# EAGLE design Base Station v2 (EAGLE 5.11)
OC_FARNELL: 1741293

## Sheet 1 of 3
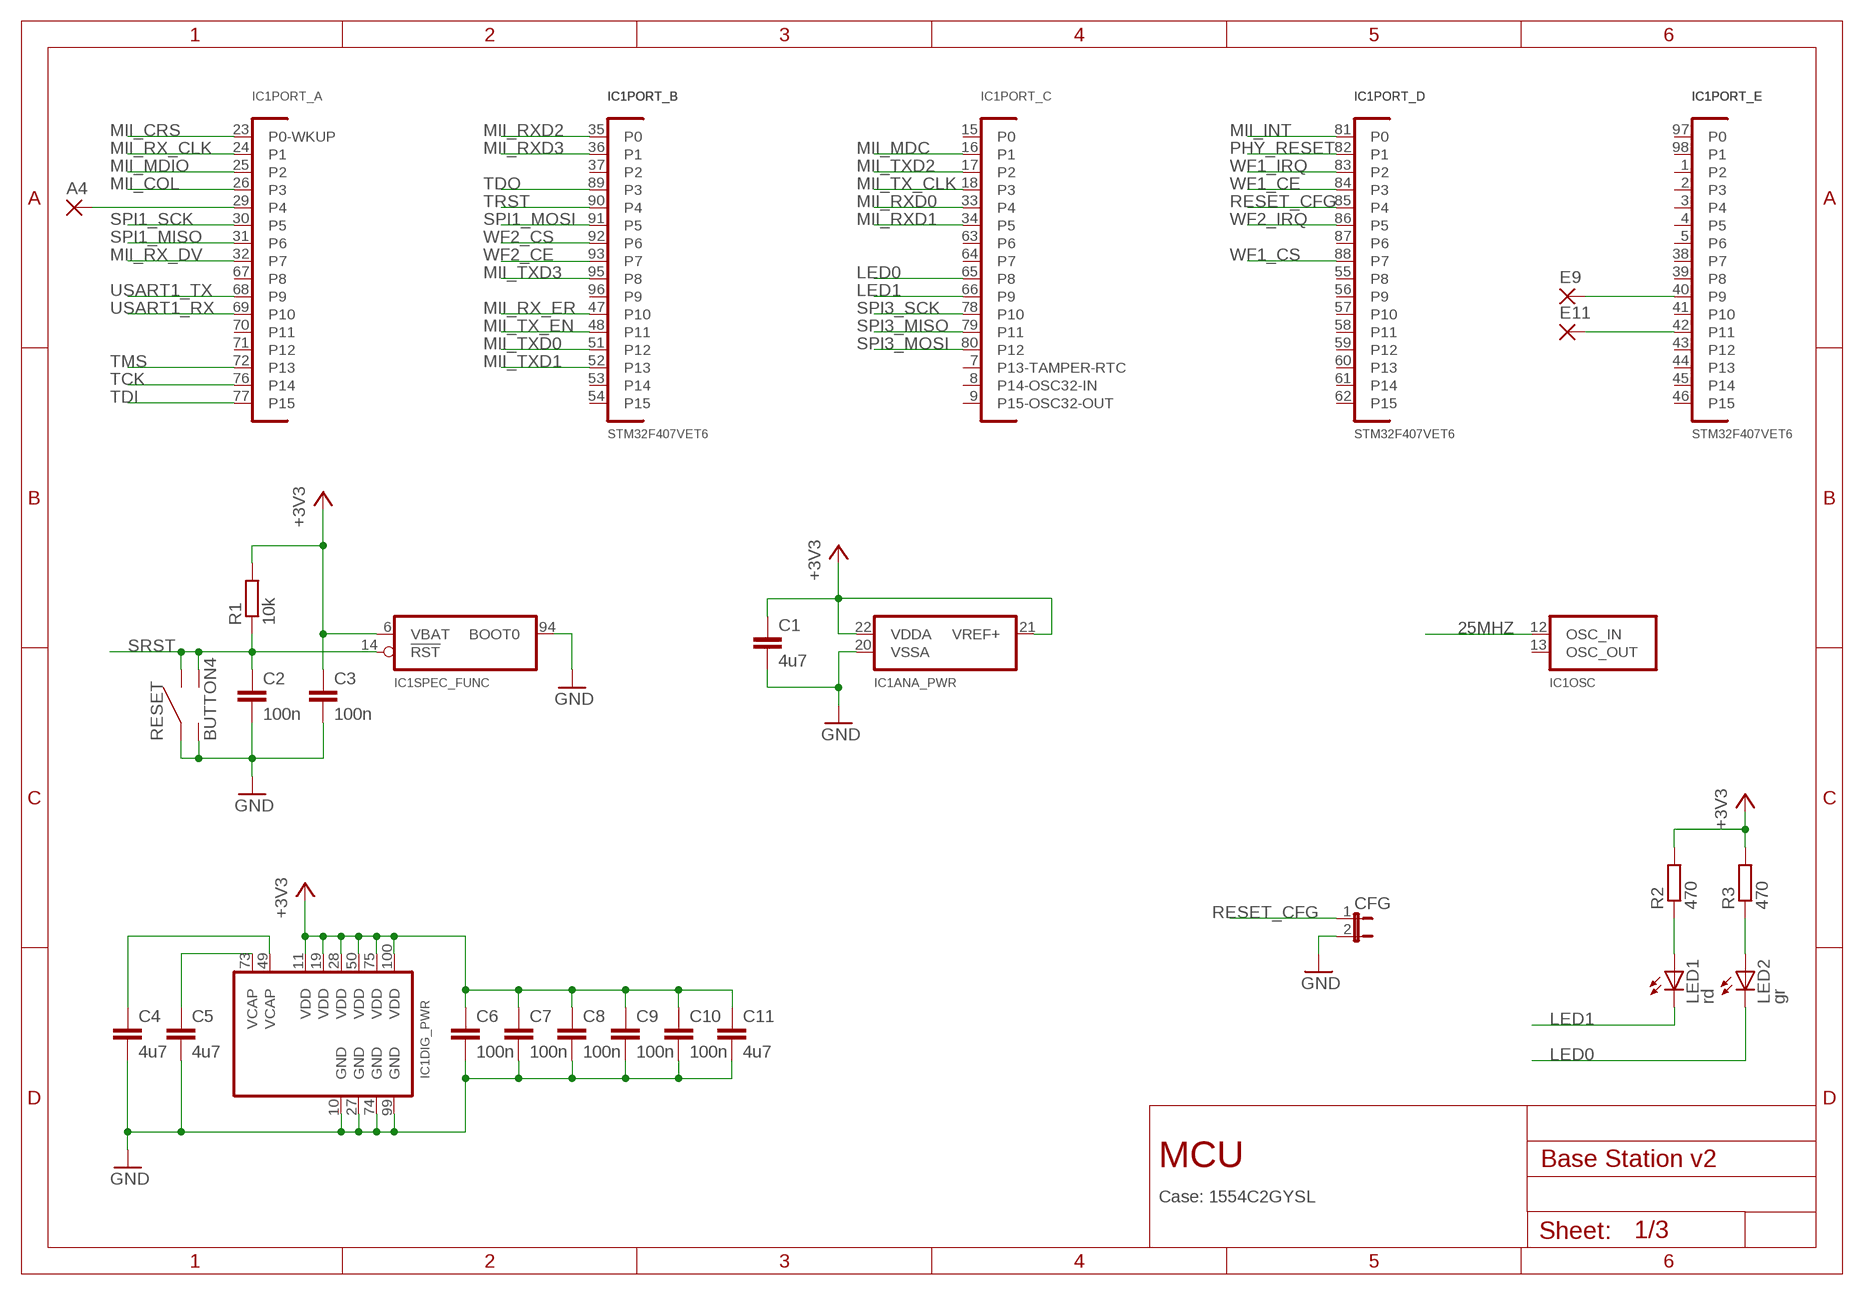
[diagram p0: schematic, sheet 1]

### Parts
A4  1,6/0,9  [1,6/0,9]
C1  4u7  C-EUC0603  [C0603]
C2  100n  C-EUC0603  [C0603]
C3  100n  C-EUC0603  [C0603]
C4  4u7  C-EUC0603  [C0603]
C5  4u7  C-EUC0603  [C0603]
C6  100n  C-EUC0603  [C0603]
C7  100n  C-EUC0603  [C0603]
C8  100n  C-EUC0603  [C0603]
C9  100n  C-EUC0603  [C0603]
C10  100n  C-EUC0603  [C0603]
C11  4u7  C-EUC0603  [C0603]
CFG  JP1E  [JP1]
E9  1,6/0,9  [1,6/0,9]
E11  1,6/0,9  [1,6/0,9]
IC1  STM32F407VET6  STM32F40_VST  [LQFP100-ST]
LED1  rd  LEDCHIP-LED0603  [CHIP-LED0603]
LED2  gr  LEDCHIP-LED0603  [CHIP-LED0603]
R1  10k  R-EU_R0603  [R0603]
R2  470  R-EU_R0603  [R0603]
R3  470  R-EU_R0603  [R0603]
RESET  BUTTON4  [BUTTON4]

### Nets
25MHZ: IC1.12(OSC:OSC_IN) ; also sheet 3
+3V3: C1.1 C3.1 C6.1 C7.1 C8.1 C9.1 C10.1 C11.1 IC1.6(SPEC_FUNC:VBAT) IC1.11(DIG_PWR:VDD) IC1.19(DIG_PWR:VDD) IC1.21(ANA_PWR:VREF+) IC1.22(ANA_PWR:VDDA) IC1.28(DIG_PWR:VDD) IC1.50(DIG_PWR:VDD) IC1.75(DIG_PWR:VDD) IC1.100(DIG_PWR:VDD) R1.2 R2.2 R3.2 ; also sheet 2,3
DAC1: A4.1(P) IC1.29(PORT_A:P4)
GND: C1.2 C2.2 C3.2 C4.2 C5.2 C6.2 C7.2 C8.2 C9.2 C10.2 C11.2 CFG.2 IC1.10(DIG_PWR:GND) IC1.20(ANA_PWR:VSSA) IC1.27(DIG_PWR:GND) IC1.74(DIG_PWR:GND) IC1.94(SPEC_FUNC:BOOT0) IC1.99(DIG_PWR:GND) RESET.1 RESET.2 ; also sheet 2,3
LED0: IC1.65(PORT_C:P8) LED2.C
LED1: IC1.66(PORT_C:P9) LED1.C
MII_COL: IC1.26(PORT_A:P3) ; also sheet 3
MII_CRS: IC1.23(PORT_A:P0-WKUP) ; also sheet 3
MII_INT: IC1.81(PORT_D:P0) ; also sheet 3
MII_MDC: IC1.16(PORT_C:P1) ; also sheet 3
MII_MDIO: IC1.25(PORT_A:P2) ; also sheet 3
MII_RX_CLK: IC1.24(PORT_A:P1) ; also sheet 3
MII_RX_DV: IC1.32(PORT_A:P7) ; also sheet 3
MII_RX_ER: IC1.47(PORT_B:P10) ; also sheet 3
MII_RXD0: IC1.33(PORT_C:P4) ; also sheet 3
MII_RXD1: IC1.34(PORT_C:P5) ; also sheet 3
MII_RXD2: IC1.35(PORT_B:P0) ; also sheet 3
MII_RXD3: IC1.36(PORT_B:P1) ; also sheet 3
MII_TX_CLK: IC1.18(PORT_C:P3) ; also sheet 3
MII_TX_EN: IC1.48(PORT_B:P11) ; also sheet 3
MII_TXD0: IC1.51(PORT_B:P12) ; also sheet 3
MII_TXD1: IC1.52(PORT_B:P13) ; also sheet 3
MII_TXD2: IC1.17(PORT_C:P2) ; also sheet 3
MII_TXD3: IC1.95(PORT_B:P8) ; also sheet 3
N$31: E9.1(P) IC1.40(PORT_E:P9)
N$32: E11.1(P) IC1.42(PORT_E:P11)
N$62: C5.1 IC1.73(DIG_PWR:VCAP)
N$63: C4.1 IC1.49(DIG_PWR:VCAP)
N$67: LED2.A R3.1
N$68: LED1.A R2.1
PHY_RESET: IC1.82(PORT_D:P1) ; also sheet 3
RESET_CFG: CFG.1 IC1.85(PORT_D:P4)
SPI1_MISO: IC1.31(PORT_A:P6) ; also sheet 2
SPI1_MOSI: IC1.91(PORT_B:P5) ; also sheet 2
SPI1_SCK: IC1.30(PORT_A:P5) ; also sheet 2
SPI3_MISO: IC1.79(PORT_C:P11) ; also sheet 2
SPI3_MOSI: IC1.80(PORT_C:P12) ; also sheet 2
SPI3_SCK: IC1.78(PORT_C:P10) ; also sheet 2
SRST: C2.1 IC1.14(SPEC_FUNC:!RST) R1.1 RESET.3 RESET.4 ; also sheet 2
TCK: IC1.76(PORT_A:P14) ; also sheet 2
TDI: IC1.77(PORT_A:P15) ; also sheet 2
TDO: IC1.89(PORT_B:P3) ; also sheet 2
TMS: IC1.72(PORT_A:P13) ; also sheet 2
TRST: IC1.90(PORT_B:P4) ; also sheet 2
USART1_RX: IC1.69(PORT_A:P10) ; also sheet 2
USART1_TX: IC1.68(PORT_A:P9) ; also sheet 2
WF1_CE: IC1.84(PORT_D:P3) ; also sheet 2
WF1_CS: IC1.88(PORT_D:P7) ; also sheet 2
WF1_IRQ: IC1.83(PORT_D:P2) ; also sheet 2
WF2_CE: IC1.93(PORT_B:P7) ; also sheet 2
WF2_CS: IC1.92(PORT_B:P6) ; also sheet 2
WF2_IRQ: IC1.86(PORT_D:P5) ; also sheet 2
Unconnected: IC1.1(PORT_E:P2) IC1.2(PORT_E:P3) IC1.3(PORT_E:P4) IC1.4(PORT_E:P5) IC1.5(PORT_E:P6) IC1.7(PORT_C:P13-TAMPER-RTC) IC1.8(PORT_C:P14-OSC32-IN) IC1.9(PORT_C:P15-OSC32-OUT) IC1.13(OSC:OSC_OUT) IC1.15(PORT_C:P0) IC1.37(PORT_B:P2) IC1.38(PORT_E:P7) IC1.39(PORT_E:P8) IC1.41(PORT_E:P10) IC1.43(PORT_E:P12) IC1.44(PORT_E:P13) IC1.45(PORT_E:P14) IC1.46(PORT_E:P15) IC1.53(PORT_B:P14) IC1.54(PORT_B:P15) IC1.55(PORT_D:P8) IC1.56(PORT_D:P9) IC1.57(PORT_D:P10) IC1.58(PORT_D:P11) IC1.59(PORT_D:P12) IC1.60(PORT_D:P13) IC1.61(PORT_D:P14) IC1.62(PORT_D:P15) IC1.63(PORT_C:P6) IC1.64(PORT_C:P7) IC1.67(PORT_A:P8) IC1.70(PORT_A:P11) IC1.71(PORT_A:P12) IC1.87(PORT_D:P6) IC1.96(PORT_B:P9) IC1.97(PORT_E:P0) IC1.98(PORT_E:P1)

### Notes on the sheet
- MCU
- Case: 1554C2GYSL

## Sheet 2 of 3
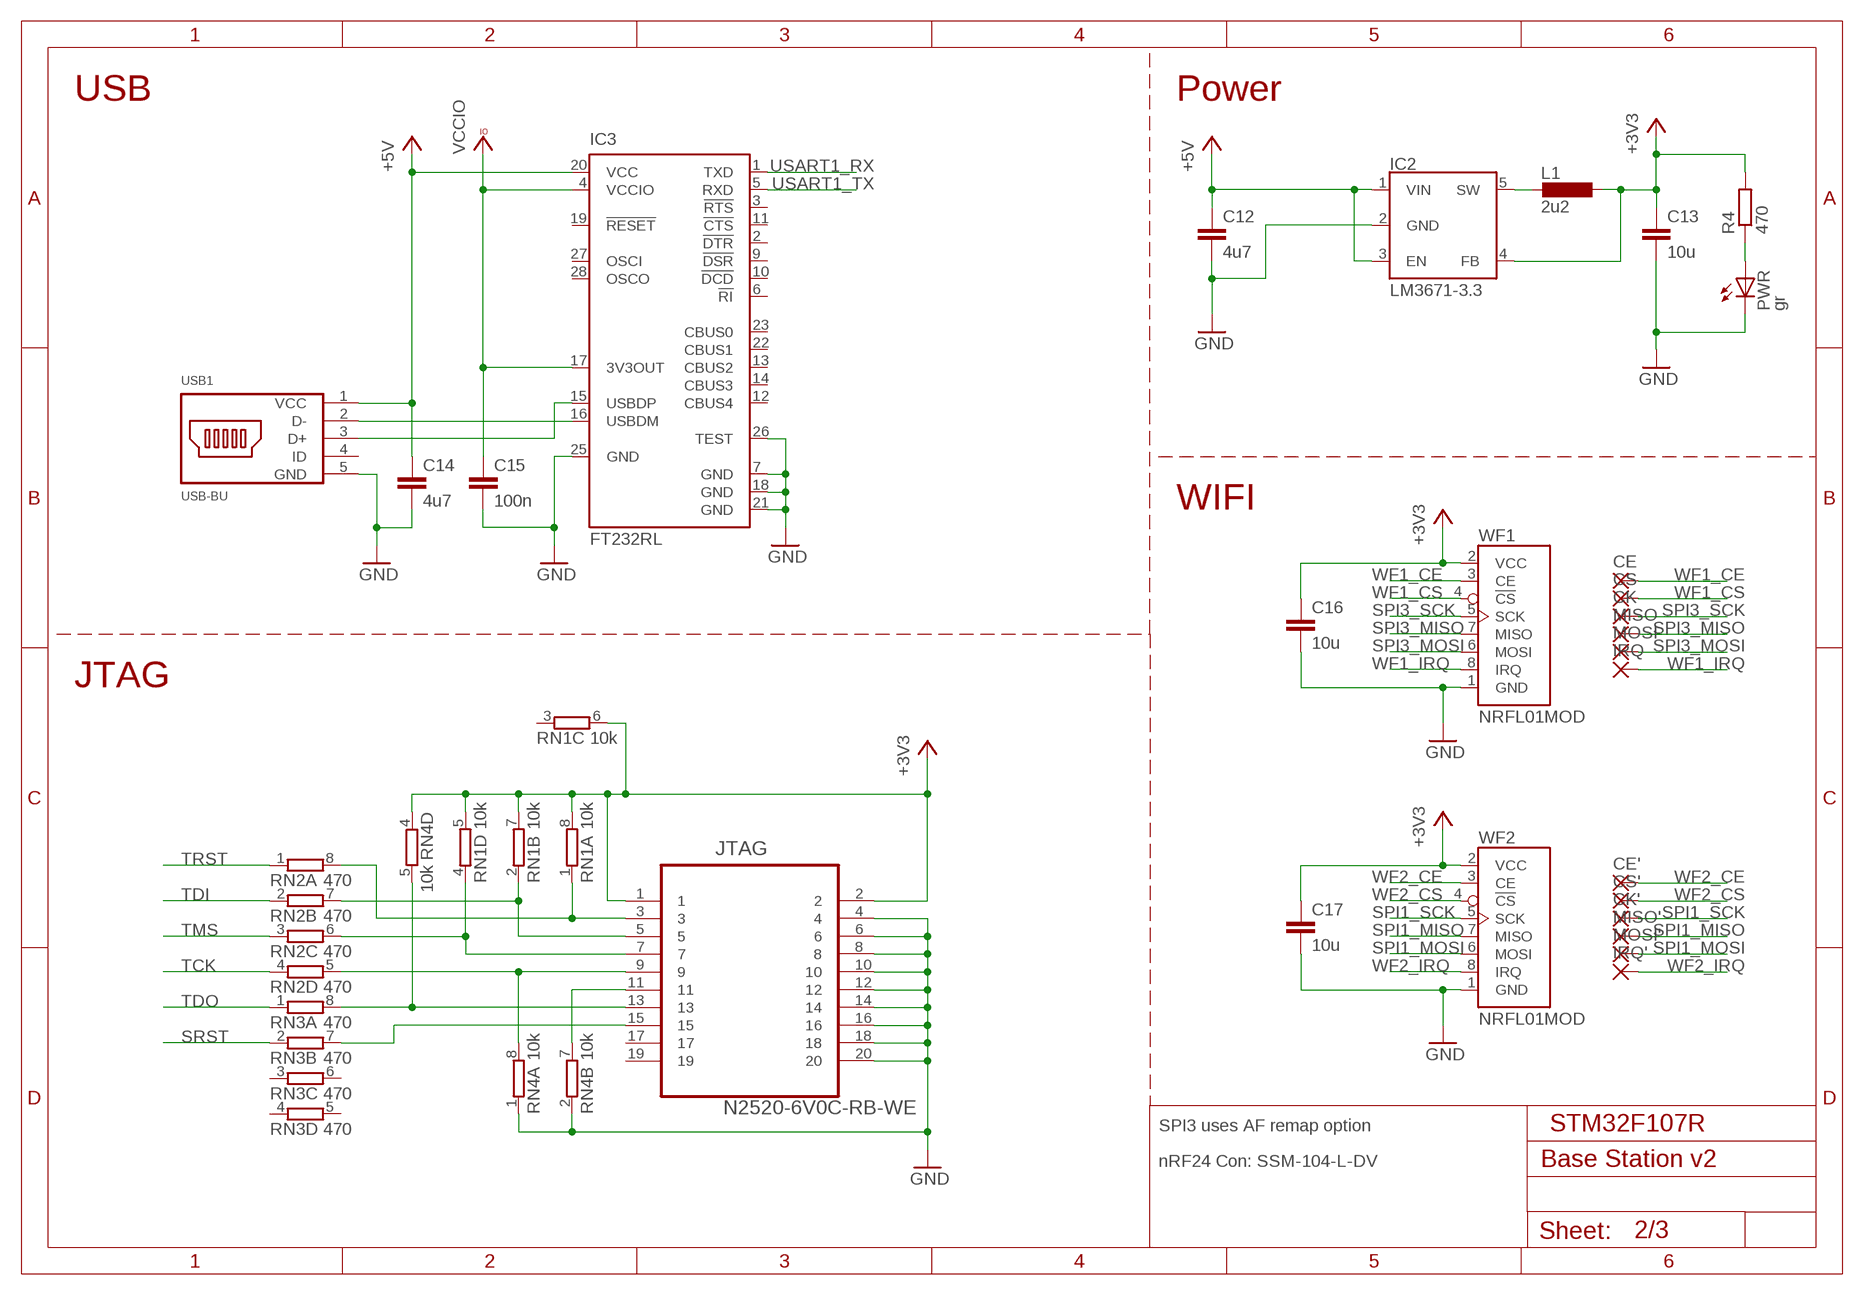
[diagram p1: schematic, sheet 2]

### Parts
C12  4u7  C-EUC0603  [C0603]
C13  10u  C-EUC0805  [C0805]
C14  4u7  C-EUC0603  [C0603]
C15  100n  C-EUC0603  [C0603]
C16  10u  C-EUC0805  [C0805]
C17  10u  C-EUC0805  [C0805]
CE  1,6/0,9  [1,6/0,9]
CE'  1,6/0,9  [1,6/0,9]
CK  1,6/0,9  [1,6/0,9]
CK'  1,6/0,9  [1,6/0,9]
CS  1,6/0,9  [1,6/0,9]
CS'  1,6/0,9  [1,6/0,9]
IC2  LM3671-3.3  LM3671  [SOT23-5]
IC3  FT232RL  [SSOP28]
IRQ  1,6/0,9  [1,6/0,9]
IRQ'  1,6/0,9  [1,6/0,9]
JTAG  N2520-6V0C-RB-WE  [3M_N2520-6V0C-RB-WE]
L1  2u2  LIHLP  [IHLP1616]
MISO  1,6/0,9  [1,6/0,9]
MISO'  1,6/0,9  [1,6/0,9]
MOSI  1,6/0,9  [1,6/0,9]
MOSI'  1,6/0,9  [1,6/0,9]
PWR  gr  LEDCHIP-LED0603  [CHIP-LED0603]
R4  470  R-EU_R0603  [R0603]
RN1  10k  4R-NEXB28V  [EXB28V]
RN2  470  4R-NEXB28V  [EXB28V]
RN3  470  4R-NEXB28V  [EXB28V]
RN4  10k  4R-NEXB28V  [EXB28V]
USB1  USB-BU  [USB-BMICRO]
WF1  NRFL01MOD  NRFL01MODN  [NRF24L01SMD]
WF2  NRFL01MOD  NRFL01MODN  [NRF24L01SMD]

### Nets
+3V3: C13.1 C16.1 C17.1 IC2.4(FB) JTAG.1 JTAG.2 L1.P$1 R4.2 RN1.5 RN1.6 RN1.7 RN1.8 RN4.4 WF1.2(VCC) WF2.2(VCC) ; also sheet 1,3
+5V: C12.1 C14.1 IC2.1(VIN) IC2.3(EN) IC3.20(VCC) USB1.1(VCC)
GND: C12.2 C13.2 C14.2 C15.2 C16.2 C17.2 IC2.2(GND) IC3.7(GND) IC3.18(GND) IC3.21(GND) IC3.25(GND) IC3.26(TEST) JTAG.4 JTAG.6 JTAG.8 JTAG.10 JTAG.12 JTAG.14 JTAG.16 JTAG.18 JTAG.20 PWR.C RN4.1 RN4.2 USB1.5(GND) WF1.1(GND) WF2.1(GND) ; also sheet 1,3
JTAG-SRST1: JTAG.15 RN3.7
JTAG-TCK1: JTAG.9 RN2.5 RN4.8
JTAG-TDI1: JTAG.5 RN1.2 RN2.7
JTAG-TDO1: JTAG.13 RN3.8 RN4.5
JTAG-TMS1: JTAG.7 RN1.4 RN2.6
JTAG-TRST1: JTAG.3 RN1.1 RN2.8
N$30: JTAG.11 RN4.7
N$41: IC3.16(USBDM) USB1.2(D-)
N$42: IC3.15(USBDP) USB1.3(D+)
N$45: IC2.5(SW) L1.P$2
N$48: PWR.A R4.1
SPI1_MISO: MISO'.1(P) WF2.7(MISO) ; also sheet 1
SPI1_MOSI: MOSI'.1(P) WF2.6(MOSI) ; also sheet 1
SPI1_SCK: CK'.1(P) WF2.5(SCK) ; also sheet 1
SPI3_MISO: MISO.1(P) WF1.7(MISO) ; also sheet 1
SPI3_MOSI: MOSI.1(P) WF1.6(MOSI) ; also sheet 1
SPI3_SCK: CK.1(P) WF1.5(SCK) ; also sheet 1
SRST: RN3.2 ; also sheet 1
TCK: RN2.4 ; also sheet 1
TDI: RN2.2 ; also sheet 1
TDO: RN3.1 ; also sheet 1
TMS: RN2.3 ; also sheet 1
TRST: RN2.1 ; also sheet 1
USART1_RX: IC3.1(TXD) ; also sheet 1
USART1_TX: IC3.5(RXD) ; also sheet 1
VCCIO: C15.1 IC3.4(VCCIO) IC3.17(3V3OUT)
WF1_CE: CE.1(P) WF1.3(CE) ; also sheet 1
WF1_CS: CS.1(P) WF1.4(!CS) ; also sheet 1
WF1_IRQ: IRQ.1(P) WF1.8(IRQ) ; also sheet 1
WF2_CE: CE'.1(P) WF2.3(CE) ; also sheet 1
WF2_CS: CS'.1(P) WF2.4(!CS) ; also sheet 1
WF2_IRQ: IRQ'.1(P) WF2.8(IRQ) ; also sheet 1
Unconnected: IC3.2(!DTR) IC3.3(!RTS) IC3.6(!RI) IC3.9(!DSR) IC3.10(!DCD) IC3.11(!CTS) IC3.12(CBUS4) IC3.13(CBUS2) IC3.14(CBUS3) IC3.19(!RESET) IC3.22(CBUS1) IC3.23(CBUS0) IC3.27(OSCI) IC3.28(OSCO) JTAG.17 JTAG.19 RN1.3 RN3.3 RN3.4 RN3.5 RN3.6 RN4.3 RN4.6 USB1.4(ID)

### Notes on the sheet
- USB | Power
- WIFI
- JTAG
- SPI3 uses AF remap option | STM32F107R
- nRF24 Con: SSM-104-L-DV

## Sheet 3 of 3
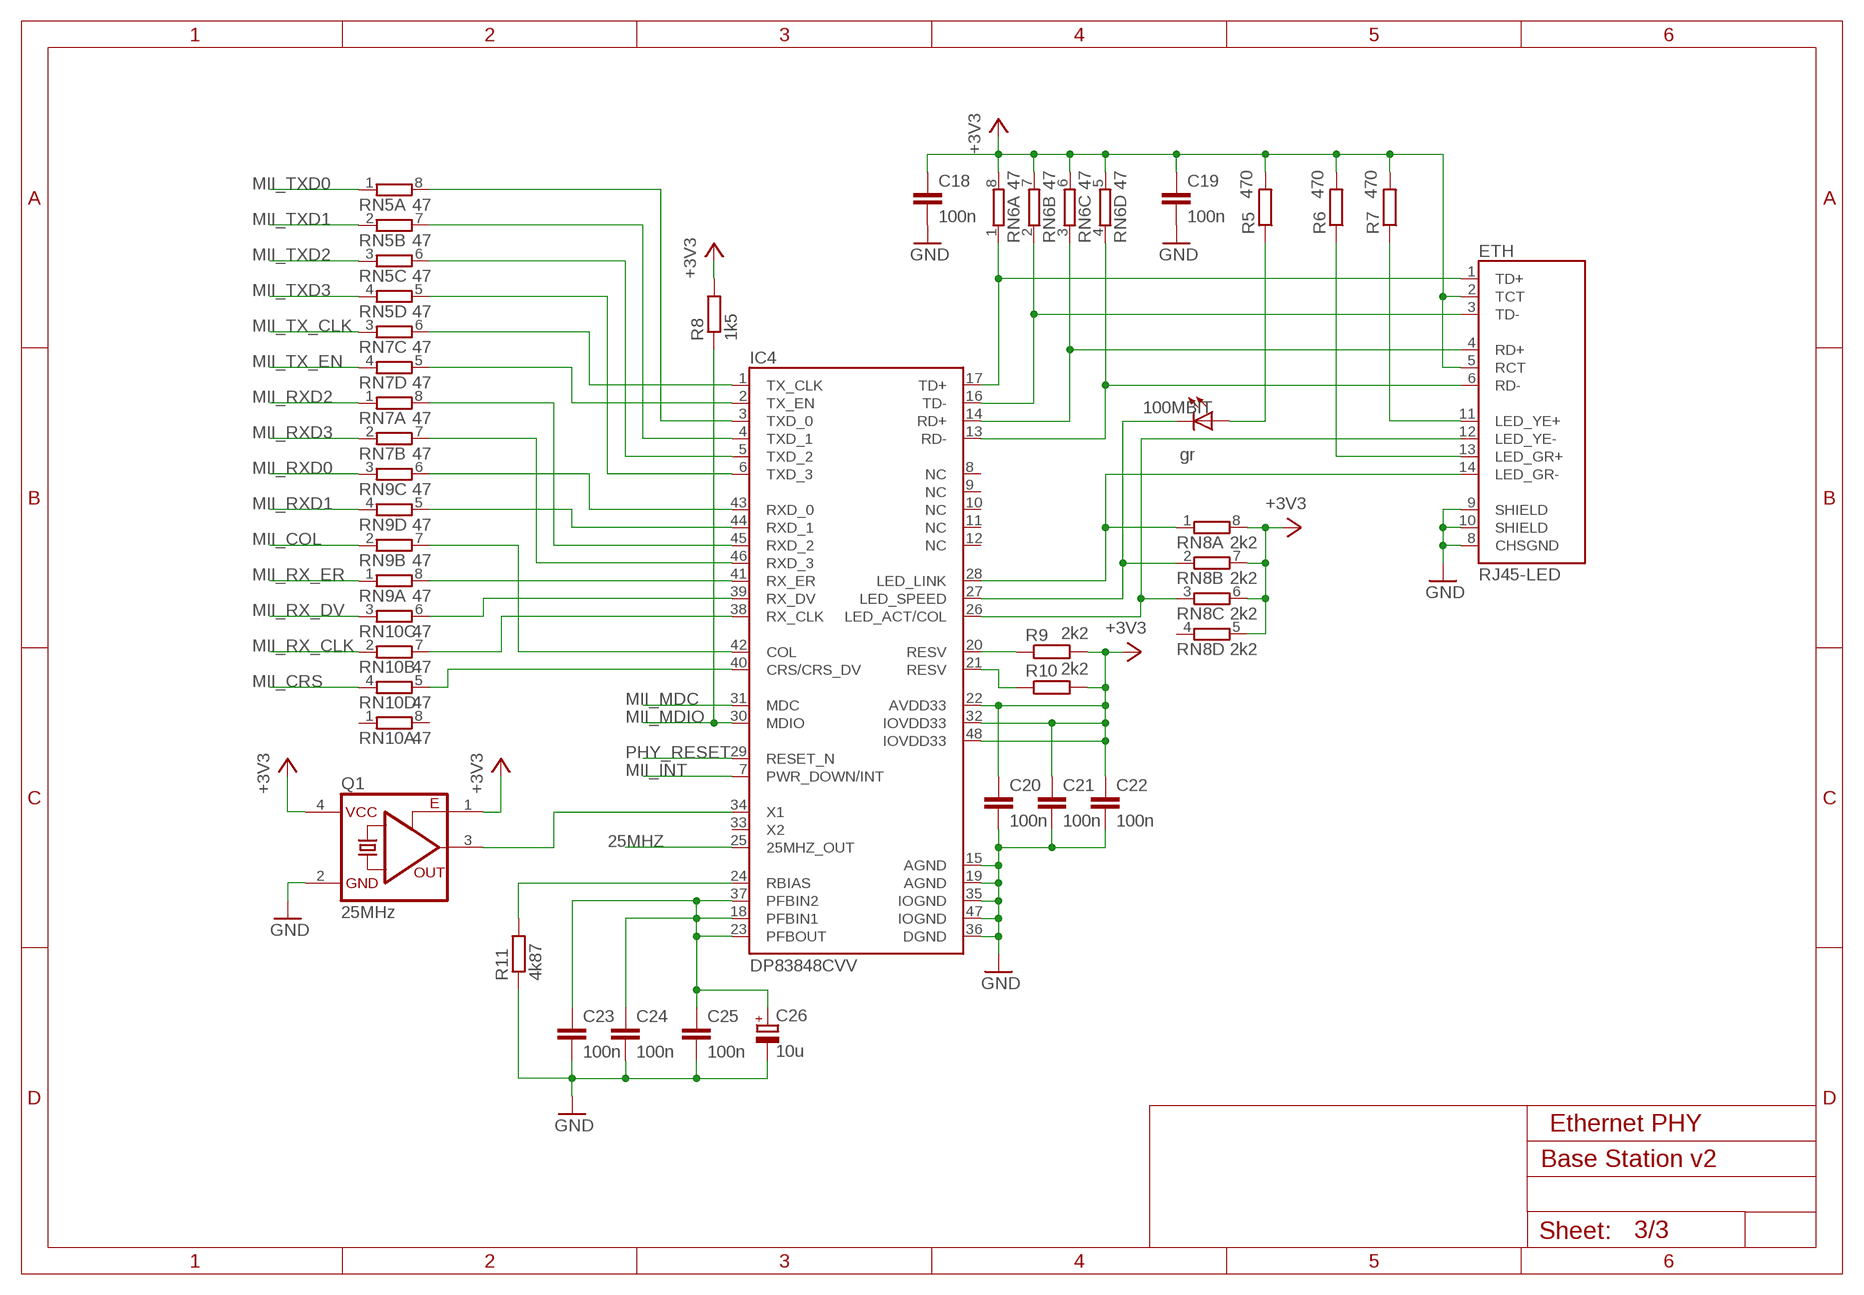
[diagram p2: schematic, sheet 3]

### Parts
100MBIT  gr  LEDCHIP-LED0603  [CHIP-LED0603]
C18  100n  C-EUC0603  [C0603]
C19  100n  C-EUC0603  [C0603]
C20  100n  C-EUC0603  [C0603]
C21  100n  C-EUC0603  [C0603]
C22  100n  C-EUC0603  [C0603]
C23  100n  C-EUC0603  [C0603]
C24  100n  C-EUC0603  [C0603]
C25  100n  C-EUC0603  [C0603]
C26  10u  CPOL-EUSMCZ  [SMC_Z]
ETH  RJ45-LED  [RJ45-LED]
IC4  DP83848CVV  DB8348C  [LQFP48]
Q1  25MHz  OSCI7X  [7X]
R5  470  R-EU_R0603  [R0603]
R6  470  R-EU_R0603  [R0603]
R7  470  R-EU_R0603  [R0603]
R8  1k5  R-EU_R0603  [R0603]
R9  2k2  R-EU_R0603  [R0603]
R10  2k2  R-EU_R0603  [R0603]
R11  4k87  R-EU_R0603  [R0603]
RN5  47  4R-NEXB28V  [EXB28V]
RN6  47  4R-NEXB28V  [EXB28V]
RN7  47  4R-NEXB28V  [EXB28V]
RN8  2k2  4R-NEXB28V  [EXB28V]
RN9  47  4R-NEXB28V  [EXB28V]
RN10  47  4R-NEXB28V  [EXB28V]

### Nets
25MHZ: IC4.25(25MHZ_OUT) ; also sheet 1
+3V3: C18.1 C19.1 C20.1 C21.1 C22.1 ETH.2(TCT) ETH.5(RCT) IC4.22(AVDD33) IC4.32(IOVDD33) IC4.48(IOVDD33) Q1.1(OE) Q1.4(VCC) R5.2 R6.2 R7.2 R8.2 R9.2 R10.2 RN6.5 RN6.6 RN6.7 RN6.8 RN8.5 RN8.6 RN8.7 RN8.8 ; also sheet 1,2
GND: C18.2 C19.2 C20.2 C21.2 C22.2 C23.2 C24.2 C25.2 C26.- ETH.8(CHSGND) ETH.9(SHIELD) ETH.10(SHIELD) IC4.15(AGND) IC4.19(AGND) IC4.35(IOGND) IC4.36(DGND) IC4.47(IOGND) Q1.2(GND) R11.1 ; also sheet 1,2
MII_COL: RN9.2 ; also sheet 1
MII_CRS: RN10.4 ; also sheet 1
MII_INT: IC4.7(PWR_DOWN/INT) ; also sheet 1
MII_MDC: IC4.31(MDC) ; also sheet 1
MII_MDIO: IC4.30(MDIO) R8.1 ; also sheet 1
MII_RX_CLK: RN10.2 ; also sheet 1
MII_RX_DV: RN10.3 ; also sheet 1
MII_RX_ER: RN9.1 ; also sheet 1
MII_RXD0: RN9.3 ; also sheet 1
MII_RXD1: RN9.4 ; also sheet 1
MII_RXD2: RN7.1 ; also sheet 1
MII_RXD3: RN7.2 ; also sheet 1
MII_TX_CLK: RN7.3 ; also sheet 1
MII_TX_EN: RN7.4 ; also sheet 1
MII_TXD0: RN5.1 ; also sheet 1
MII_TXD1: RN5.2 ; also sheet 1
MII_TXD2: RN5.3 ; also sheet 1
MII_TXD3: RN5.4 ; also sheet 1
N$1: IC4.3(TXD_0) RN5.8
N$2: IC4.4(TXD_1) RN5.7
N$3: IC4.5(TXD_2) RN5.6
N$4: IC4.6(TXD_3) RN5.5
N$5: IC4.1(TX_CLK) RN7.6
N$6: IC4.2(TX_EN) RN7.5
N$7: IC4.45(RXD_2) RN7.8
N$8: IC4.46(RXD_3) RN7.7
N$9: IC4.43(RXD_0) RN9.6
N$10: IC4.44(RXD_1) RN9.5
N$11: IC4.42(COL) RN9.7
N$12: IC4.41(RX_ER) RN9.8
N$13: IC4.39(RX_DV) RN10.6
N$14: IC4.38(RX_CLK) RN10.7
N$15: IC4.40(CRS/CRS_DV) RN10.5
N$16: IC4.20(RESV) R9.1
N$17: ETH.13(LED_GR+) R6.1
N$18: IC4.34(X1) Q1.3(FO)
N$19: ETH.11(LED_YE+) R7.1
N$20: IC4.24(RBIAS) R11.2
N$21: C23.1 C24.1 C25.1 C26.+ IC4.18(PFBIN1) IC4.23(PFBOUT) IC4.37(PFBIN2)
N$22: IC4.21(RESV) R10.1
N$23: ETH.12(LED_YE-) IC4.26(LED_ACT/COL) RN8.3
N$24: 100MBIT.C IC4.27(LED_SPEED) RN8.2
N$25: ETH.14(LED_GR-) IC4.28(LED_LINK) RN8.1
N$26: ETH.6(RD-) IC4.13(RD-) RN6.4
N$27: ETH.4(RD+) IC4.14(RD+) RN6.3
N$28: ETH.3(TD-) IC4.16(TD-) RN6.2
N$29: ETH.1(TD+) IC4.17(TD+) RN6.1
N$33: 100MBIT.A R5.1
PHY_RESET: IC4.29(RESET_N) ; also sheet 1
Unconnected: IC4.8(NC) IC4.9(NC) IC4.10(NC) IC4.11(NC) IC4.12(NC) IC4.33(X2) RN8.4 RN10.1 RN10.8

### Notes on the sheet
- Ethernet PHY

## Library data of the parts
100MBIT LED1 LED2 PWR = led:LED: LED
A4 CE CE' CK CK' CS CS' E9 E11 IRQ IRQ' MISO MISO' MOSI MOSI' = wirepad:1,6/0,9: THROUGH-HOLE PAD
C1-C25 = rcl:C-EU: CAPACITOR, European symbol
C26 = rcl:CPOL-EU: POLARIZED CAPACITOR, European symbol
CFG = jumper:JP1E: JUMPER
ETH = Marvin:RJ45-LED
IC1 = Marvin:STM32F40_V: 168 MHz, 192KB RAM, 1024 KB Flash
IC2 = Marvin:LM3671
IC3 = ftdichip:FT232R: Source: http://www.ftdichip.com/Documents/DataSheets/DS_FT232R_v104.pdf; MPN: FT232RL; OC_FARNELL: 1146032; OC_NEWARK: 91K9918
IC4 = Marvin:DB8348C
JTAG = Marvin:N2520-6V0C-RB-WE: Header; MPN: N2520-6V0C-RB-WE; OC_FARNELL: 1428504; OC_NEWARK: 34P5344; PACKAGE: Header-20Pin; SUPPLIER: 3M
L1 = Marvin:L
Q1 = Marvin:OSCI
R1-R11 = rcl:R-EU_: RESISTOR, European symbol
RESET = Marvin:BUTTON4: Tyco Push Button FSM2JSMA Farnell Order: 3801287
RN1-RN10 = resistor-dil:4R-N: Array Chip Resistor Source: RS Component / Phycomp; OC_FARNELL: unknown; OC_NEWARK: unknown
USB1 = Marvin:USB-B: USB Connector Micro: Molex 47346-0001
WF1 WF2 = Marvin:NRFL01MOD

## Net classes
0 default: width 0.152 mm, clearance 0.152 mm

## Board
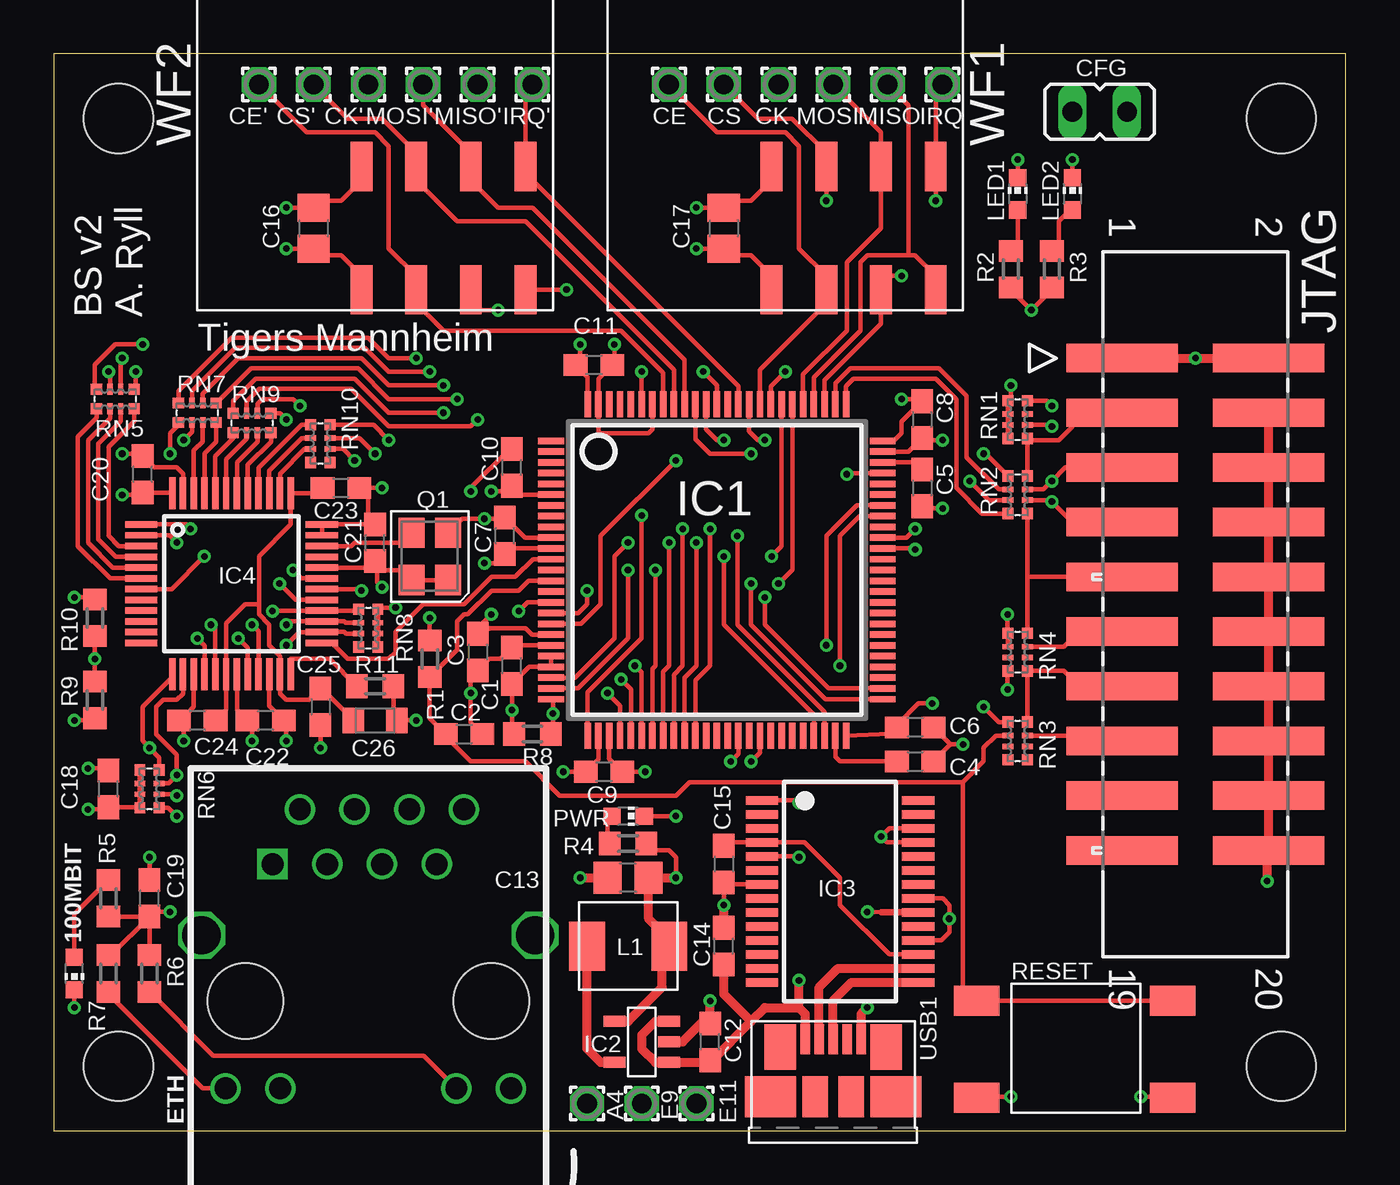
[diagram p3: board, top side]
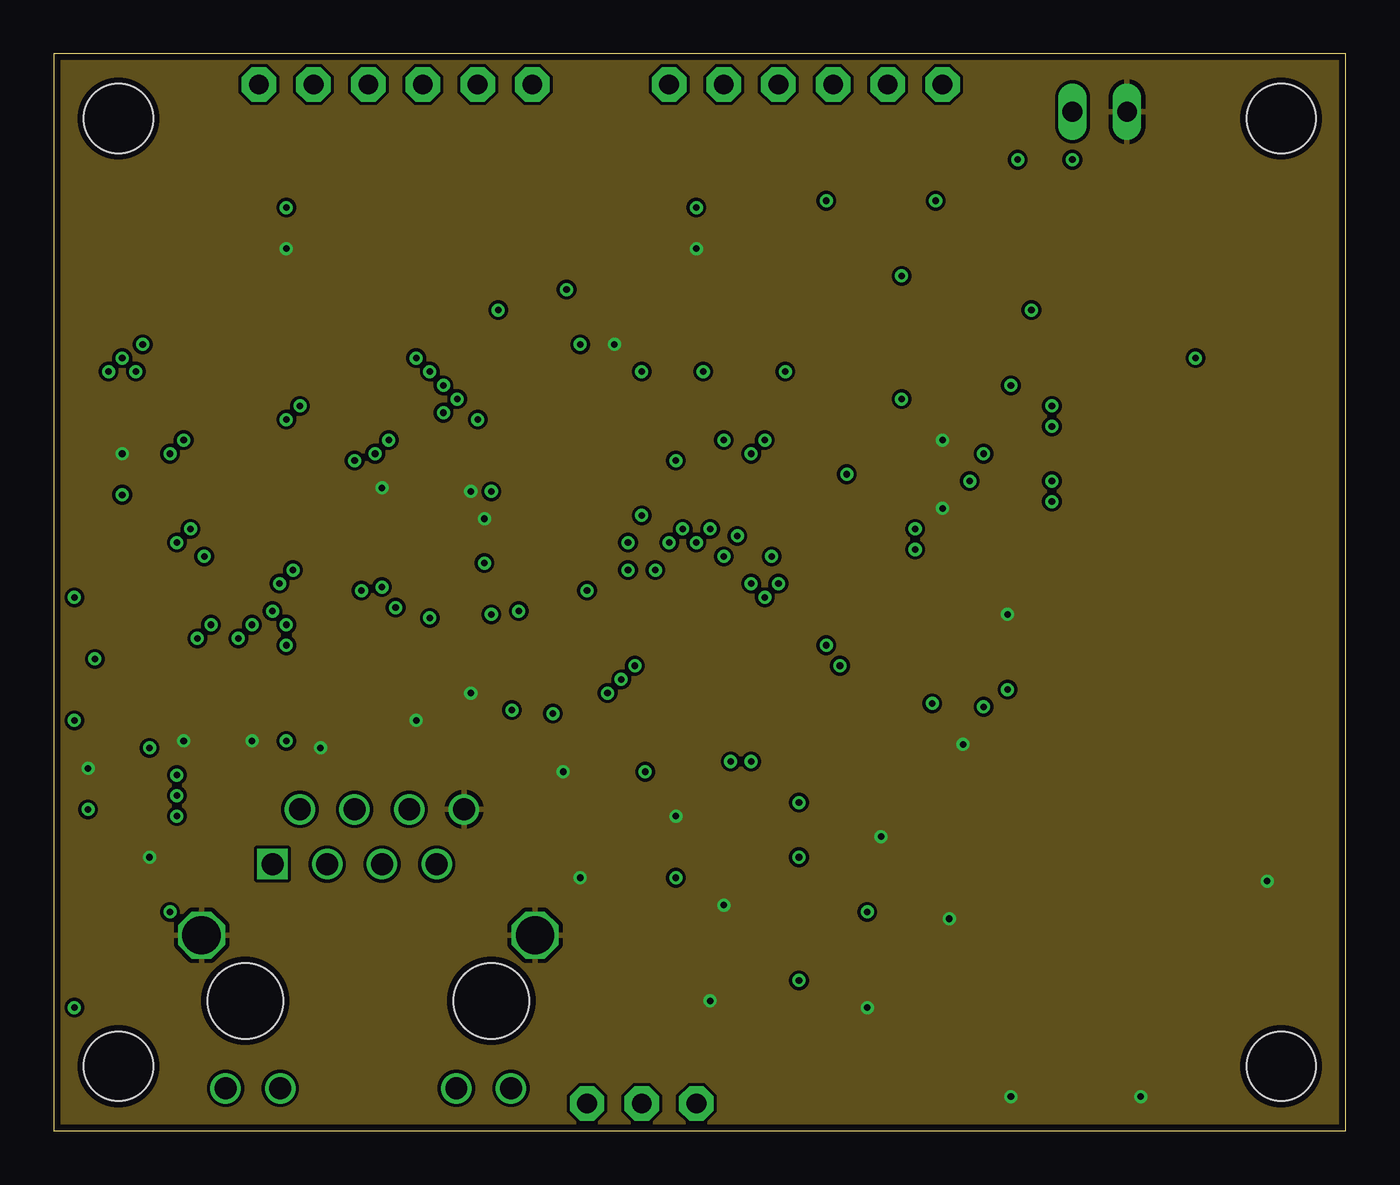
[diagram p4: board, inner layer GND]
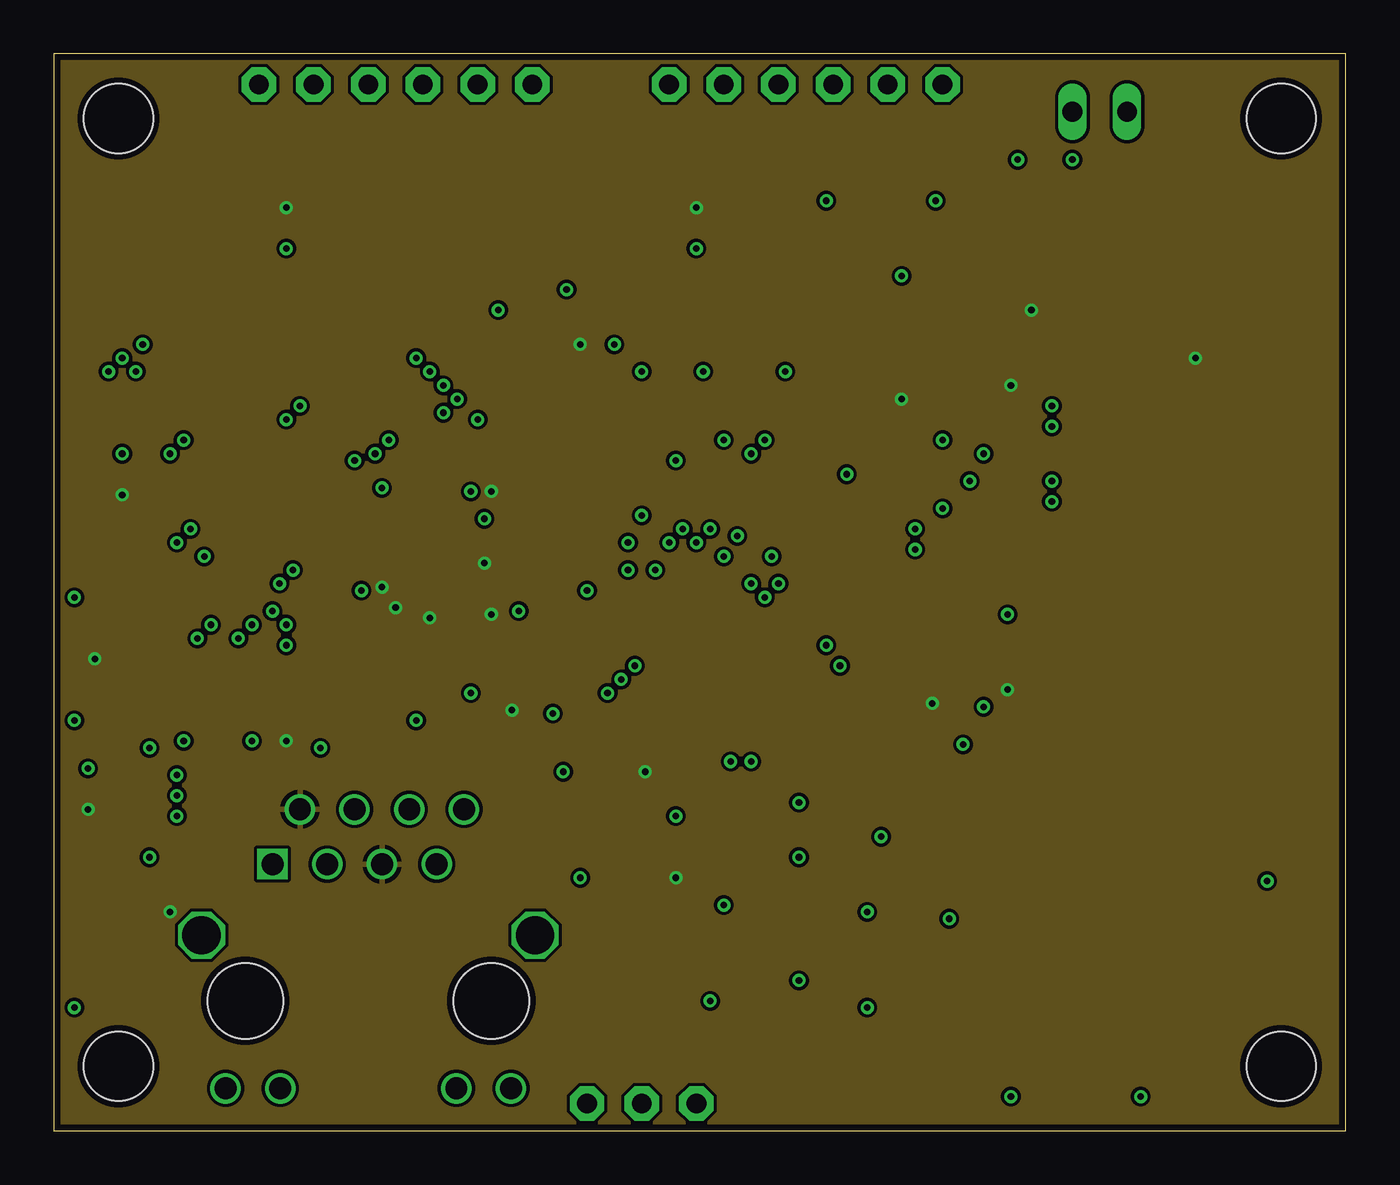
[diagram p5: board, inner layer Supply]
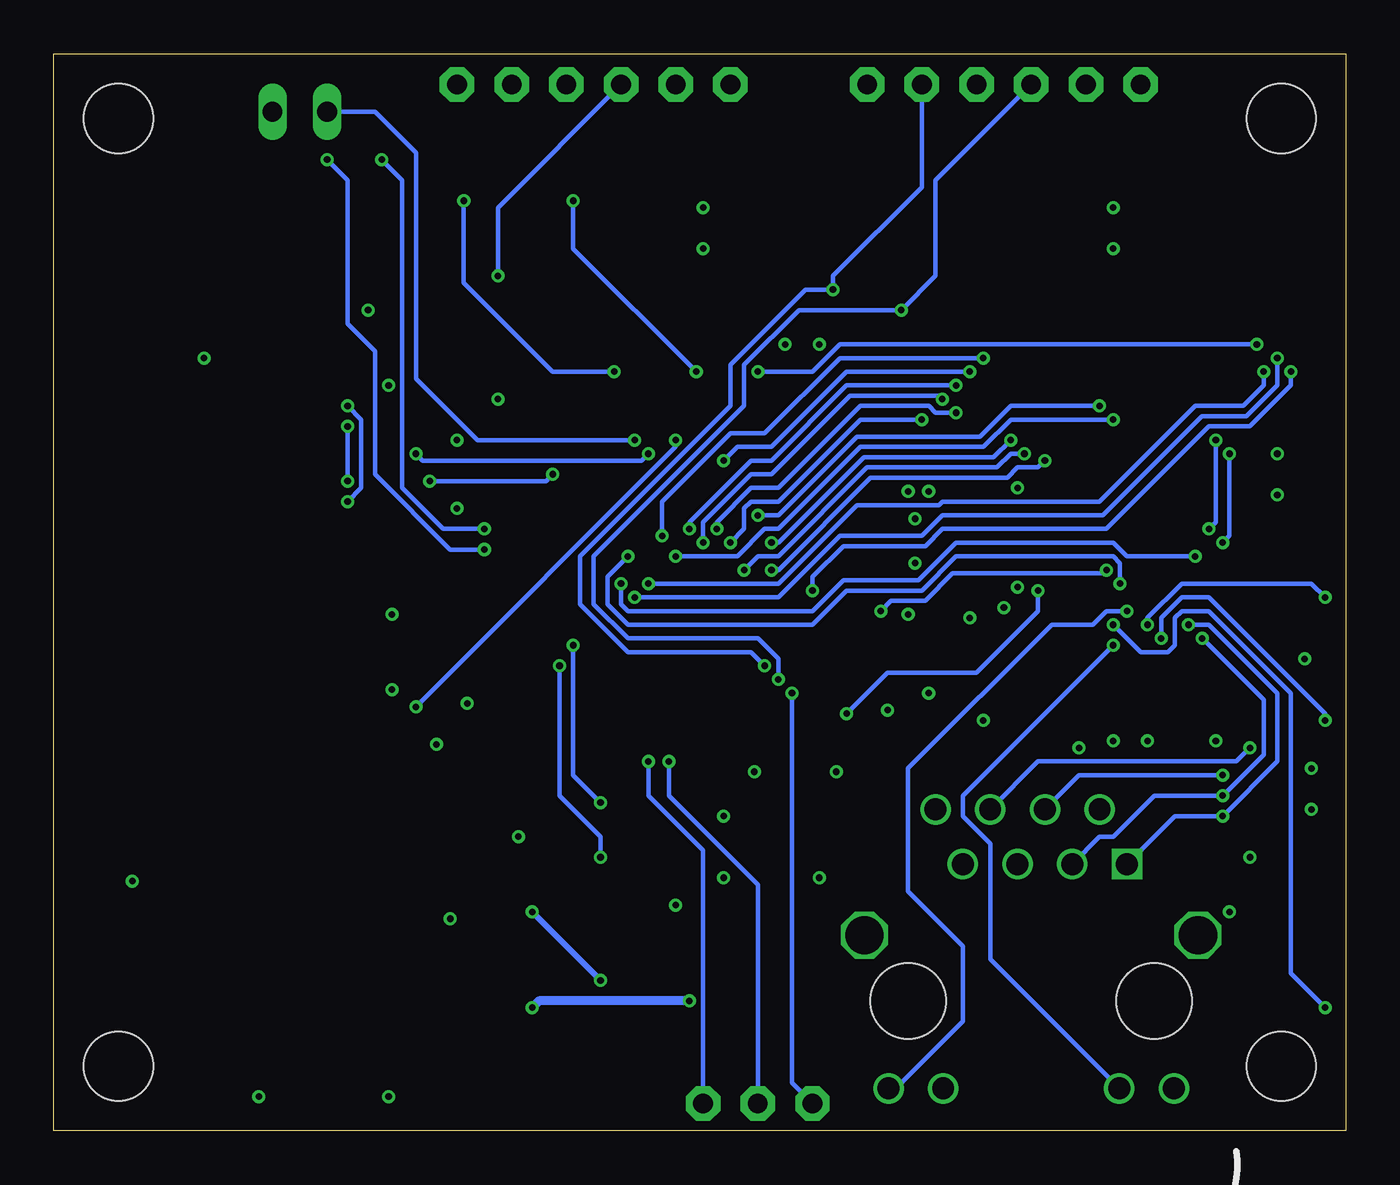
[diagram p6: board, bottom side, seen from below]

Size 60 x 50 mm. Coordinates in mm from the lower left corner, seen from the top.
Outline: 0,0 60,0 60,50 0,50 0,0
Copper layers (1+2*15+16): Top 0.035mm / dielectric 1.5mm / GND 0.035mm / dielectric 0.15mm / Supply 0.035mm / dielectric 0.2mm / Bottom 0.035mm
Design rules "PCB-POOL Standard *": minimum track width 0.15mm, minimum drill 0.3mm, track to track 0.15mm, track to pad 0.15mm, pad to pad 0.15mm, via to via 0.15mm, smd to smd 0.15mm, copper to edge 0.3mm, drill to drill 0.2mm, minimum pad ring 0.2mm, minimum via ring 0.15mm, stop-mask expansion 0.05mm, vias tented up to drill 0mil, thermal gap 0.2mm
Holes 3.2 mm at 57,47 3,3 3,47 57,3
tKeepout: area 0,0 to 6,6; area 0,49 to 6,55; area 54,44 to 60,50; area 54,0 to 60,6

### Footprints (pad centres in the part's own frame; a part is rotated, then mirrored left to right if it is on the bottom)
CHIP-LED0603 = smd 0.8 x 0.8: A 0,-0.75; C 0,0.75
1,6/0,9 = drill 0.914 pad 1.6 octagon: 1 0,0
C0603 = smd 1.1 x 1: 1 -0.85,0; 2 0.85,0
C0805 = smd 1.3 x 1.5: 1 -0.95,0; 2 0.95,0
SMC_Z = smd 1 x 1.2: + -1,0; - 1,0
JP1 = drill 0.914 long: 1 0,-1.27; 2 0,1.27
RJ45-LED = drill 1.016 square: 1 -4.445,6.35 | drill 1.016 round: 2 -3.175,8.89; 3 -1.905,6.35; 4 -0.635,8.89; 5 0.635,6.35; 6 1.905,8.89; 7 3.175,6.35; 8 4.445,8.89; 11 -6.629,-4.064; 12 -4.089,-4.064; 13 4.089,-4.064; 14 6.629,-4.064 | drill 1.778 octagon: 9 -7.747,3.048; 10 7.747,3.048 | hole 3.5: -5.715,0; 5.715,0
LQFP100-ST = smd 0.3 x 1.2: 1 -6,-7.7; 2 -5.5,-7.7; 3 -5,-7.7; 4 -4.5,-7.7; 5 -4,-7.7; 6 -3.5,-7.7; 7 -3,-7.7; 8 -2.5,-7.7; 9 -2,-7.7; 10 -1.5,-7.7; 11 -1,-7.7; 12 -0.5,-7.7; 13 0,-7.7; 14 0.5,-7.7; 15 1,-7.7; 16 1.5,-7.7; 17 2,-7.7; 18 2.5,-7.7; 19 3,-7.7; 20 3.5,-7.7; 21 4,-7.7; 22 4.5,-7.7; 23 5,-7.7; 24 5.5,-7.7; 25 6,-7.7; 51 6,7.7; 52 5.5,7.7; 53 5,7.7; 54 4.5,7.7; 55 4,7.7; 56 3.5,7.7; 57 3,7.7; 58 2.5,7.7; 59 2,7.7; 60 1.5,7.7; 61 1,7.7; 62 0.5,7.7; 63 0,7.7; 64 -0.5,7.7; 65 -1,7.7; 66 -1.5,7.7; 67 -2,7.7; 68 -2.5,7.7; 69 -3,7.7; 70 -3.5,7.7; 71 -4,7.7; 72 -4.5,7.7; 73 -5,7.7; 74 -5.5,7.7; 75 -6,7.7 | smd 1.2 x 0.3: 26 7.7,-6; 27 7.7,-5.5; 28 7.7,-5; 29 7.7,-4.5; 30 7.7,-4; 31 7.7,-3.5; 32 7.7,-3; 33 7.7,-2.5; 34 7.7,-2; 35 7.7,-1.5; 36 7.7,-1; 37 7.7,-0.5; 38 7.7,0; 39 7.7,0.5; 40 7.7,1; 41 7.7,1.5; 42 7.7,2; 43 7.7,2.5; 44 7.7,3; 45 7.7,3.5; 46 7.7,4; 47 7.7,4.5; 48 7.7,5; 49 7.7,5.5; 50 7.7,6; 76 -7.7,6; 77 -7.7,5.5; 78 -7.7,5; 79 -7.7,4.5; 80 -7.7,4; 81 -7.7,3.5; 82 -7.7,3; 83 -7.7,2.5; 84 -7.7,2; 85 -7.7,1.5; 86 -7.7,1; 87 -7.7,0.5; 88 -7.7,0; 89 -7.7,-0.5; 90 -7.7,-1; 91 -7.7,-1.5; 92 -7.7,-2; 93 -7.7,-2.5; 94 -7.7,-3; 95 -7.7,-3.5; 96 -7.7,-4; 97 -7.7,-4.5; 98 -7.7,-5; 99 -7.7,-5.5; 100 -7.7,-6
SOT23-5 = smd 1.016 x 0.508: 1 -1.27,0.953; 2 -1.27,0; 3 -1.27,-0.953; 4 1.27,-0.953; 5 1.27,0.953
SSOP28 = smd 0.4 x 1.5: 1 -4.225,-3.625; 2 -3.575,-3.625; 3 -2.925,-3.625; 4 -2.275,-3.625; 5 -1.625,-3.625; 6 -0.975,-3.625; 7 -0.325,-3.625; 8 0.325,-3.625; 9 0.975,-3.625; 10 1.625,-3.625; 11 2.275,-3.625; 12 2.925,-3.625; 13 3.575,-3.625; 14 4.225,-3.625; 15 4.225,3.625; 16 3.575,3.625; 17 2.925,3.625; 18 2.275,3.625; 19 1.625,3.625; 20 0.975,3.625; 21 0.325,3.625; 22 -0.325,3.625; 23 -0.975,3.625; 24 -1.625,3.625; 25 -2.275,3.625; 26 -2.925,3.625; 27 -3.575,3.625; 28 -4.225,3.625
LQFP48 = smd 1.5 x 0.3: 1 -4.2,2.75; 2 -4.2,2.25; 3 -4.2,1.75; 4 -4.2,1.25; 5 -4.2,0.75; 6 -4.2,0.25; 7 -4.2,-0.25; 8 -4.2,-0.75; 9 -4.2,-1.25; 10 -4.2,-1.75; 11 -4.2,-2.25; 12 -4.2,-2.75; 25 4.2,-2.75; 26 4.2,-2.25; 27 4.2,-1.75; 28 4.2,-1.25; 29 4.2,-0.75; 30 4.2,-0.25; 31 4.2,0.25; 32 4.2,0.75; 33 4.2,1.25; 34 4.2,1.75; 35 4.2,2.25; 36 4.2,2.75 | smd 0.3 x 1.5: 13 -2.75,-4.2; 14 -2.25,-4.2; 15 -1.75,-4.2; 16 -1.25,-4.2; 17 -0.75,-4.2; 18 -0.25,-4.2; 19 0.25,-4.2; 20 0.75,-4.2; 21 1.25,-4.2; 22 1.75,-4.2; 23 2.25,-4.2; 24 2.75,-4.2; 37 2.75,4.2; 38 2.25,4.2; 39 1.75,4.2; 40 1.25,4.2; 41 0.75,4.2; 42 0.25,4.2; 43 -0.25,4.2; 44 -0.75,4.2; 45 -1.25,4.2; 46 -1.75,4.2; 47 -2.25,4.2; 48 -2.75,4.2
3M_N2520-6V0C-RB-WE = smd 1.321 x 5.182: 1 -11.43,-3.404; 2 -11.43,3.404; 3 -8.89,-3.404; 4 -8.89,3.404; 5 -6.35,-3.404; 6 -6.35,3.404; 7 -3.81,-3.404; 8 -3.81,3.404; 9 -1.27,-3.404; 10 -1.27,3.404; 11 1.27,-3.404; 12 1.27,3.404; 13 3.81,-3.404; 14 3.81,3.404; 15 6.35,-3.404; 16 6.35,3.404; 17 8.89,-3.404; 18 8.89,3.404; 19 11.43,-3.404; 20 11.43,3.404
IHLP1616 = smd 1.651 x 2.286: P$1 -1.905,0; P$2 1.905,0
7X = smd 1.4 x 1.2: 1 -1.1,-0.85; 2 1.1,-0.85; 3 1.1,0.85; 4 -1.1,0.85
R0603 = smd 1 x 1.1: 1 -0.85,0; 2 0.85,0
BUTTON4 = smd 1.4 x 2.1: 1 4.5,9.1; 2 4.5,0; 3 0,9.1; 4 0,0
EXB28V = smd 0.525 x 0.5: 1 -0.875,-0.45; 4 0.875,-0.45; 5 0.875,0.45; 8 -0.875,0.45 | smd 0.25 x 0.5: 2 -0.25,-0.45; 3 0.25,-0.45; 6 0.25,0.45; 7 -0.25,0.45
USB-BMICRO = smd 0.45 x 1.38: 1 1.3,-2.66; 2 0.65,-2.66; 3 0,-2.66; 4 -0.65,-2.66; 5 -1.3,-2.66 | smd 1.175 x 1.9: P$1 0.838,0; P$2 -0.838,0 | smd 2.375 x 1.9: P$3 2.913,0; P$4 -2.913,0 | smd 1.475 x 2.1: P$5 -2.462,-2.3; P$6 2.462,-2.3
NRF24L01SMD = smd 1.016 x 2.286: 1 -3.81,-2.857; 2 -3.81,2.857; 3 -1.27,-2.857; 4 -1.27,2.857; 5 1.27,-2.857; 6 1.27,2.857; 7 3.81,-2.857; 8 3.81,2.857

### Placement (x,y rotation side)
100MBIT  0.95,7.3 180 top
A4  24.77,1.27 0 top
C1  21.27,21.59 90 top
C2  19.05,18.41 0 top
C3  19.68,22.23 270 top
C4  40.01,17.14 0 top
C5  40.32,29.84 270 top
C6  40.01,18.73 0 top
C7  20.95,27.62 90 top
C8  40.32,33.02 270 top
C9  25.56,16.67 180 top
C10  21.27,30.8 90 top
C11  25.08,35.56 0 top
C12  30.48,4.13 90 top
C13  26.67,11.75 180 top
C14  31.11,8.57 90 top
C15  31.11,12.38 270 top
C16  12.06,41.91 270 top
C17  31.11,41.91 270 top
C18  2.54,15.88 90 top
C19  4.45,10.79 90 top
C20  4.13,30.48 90 top
C21  14.92,27.3 90 top
C22  9.84,19.05 180 top
C23  13.34,29.84 0 top
C24  6.67,19.05 180 top
C25  12.38,19.68 270 top
C26  14.92,19.05 0 top
CE  28.57,48.58 0 top
CE'  9.53,48.58 270 top
CFG  48.58,47.31 270 top
CK  33.66,48.58 0 top
CK'  14.61,48.58 270 top
CS  31.11,48.58 0 top
CS'  12.06,48.58 270 top
E9  27.3,1.27 0 top
E11  29.84,1.27 0 top
ETH  14.61,6.03 0 top
IC1  30.8,26.04 270 top
IC2  27.3,4.13 180 top
IC3  36.51,11.11 270 top
IC4  8.26,25.4 0 top
IRQ  41.27,48.58 0 top
IRQ'  22.23,48.58 270 top
JTAG  53.02,24.45 270 top
L1  26.67,8.57 180 top
LED1  44.77,43.5 0 top
LED2  47.31,43.5 0 top
MISO  38.73,48.58 0 top
MISO'  19.68,48.58 270 top
MOSI  36.2,48.58 0 top
MOSI'  17.14,48.58 270 top
PWR  26.67,14.61 270 top
Q1  17.46,26.67 90 top
R1  17.46,21.91 90 top
R2  44.45,40.01 270 top
R3  46.35,40.01 270 top
R4  26.67,13.34 0 top
R5  2.54,10.79 270 top
R6  4.45,7.3 90 top
R7  2.54,7.3 90 top
R8  22.23,18.41 180 top
R9  1.91,20 90 top
R10  1.91,23.81 270 top
R11  14.92,20.64 180 top
RESET  42.86,6.03 270 top
RN1  44.77,33.02 90 top
RN2  44.77,29.53 270 top
RN3  44.77,18.1 270 top
RN4  44.77,22.23 270 top
RN5  2.86,33.97 180 top
RN6  4.45,15.88 90 top
RN7  6.67,33.34 180 top
RN8  14.61,23.34 270 top
RN9  9.21,32.86 180 top
RN10  12.38,31.91 90 top
USB1  36.2,1.59 180 top
WF1  37.15,41.91 0 top
WF2  18.1,41.91 0 top

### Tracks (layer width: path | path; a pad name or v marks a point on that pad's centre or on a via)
25MHZ
  Top 0.203: IC4.25 12.91,22.65 13.65,21.91 15.56,21.91 15.88,22.23 15.88,23.18 17.14,24.45 19.05,24.45 20.32,25.72 21.43,25.72 22.25,26.54 IC1.12
+3V3  (via drill 0.3)
  Top 0.203: v3.17,29.53 4.03,29.53 C20.1 5.47,29.63 IC4.48 | IC4.22 10.01,19.74 C22.1 10.79,18.95 v10.79,18.1 | RN8.5 RN8.6 RN8.7 RN8.8 15.13,24.29 v15.88,24.29 | IC4.32 14.62,26.15 C21.1 15.03,26.04 | 15.03,26.04 16.19,26.04 16.61,25.61 Q1.4 Q1.1 | 15.03,26.04 15.03,25.46 v15.24,25.24 | IC1.19 22.21,23.04 21.91,23.34 20.26,23.34 C3.1 19.68,23.34 v20.32,23.97 | IC1.21 IC1.22 22.07,21.54 C1.1 v21.27,19.53 21.27,18.52 R8.2 | IC1.28 25.8,17.28 C9.1 | v20,26.35 20.69,26.35 C7.1 21.22,27.04 IC1.11 | C9.1 | C9.1 v27.46,16.67 | v20.32,29.69 21.01,29.69 C10.1 21.68,29.54 IC1.6 | IC1.100 24.8,34.99 C11.1 24.45,35.77 v24.45,36.51 | R1.2 v17.46,23.81 | IC1.75 39.02,32.03 39.37,32.38 39.37,32.92 C8.1 40.22,33.97 v39.37,33.97 | IC1.50 38.86,18.43 C6.1 39.16,18.84 40.16,19.84 v40.8,19.84 | WF1.2 33.34,44.13 32.38,43.18 31.54,43.18 C17.1 31.01,42.86 v29.84,42.86 | WF2.2 14.29,44.13 13.34,43.18 12.48,43.18 C16.1 11.96,42.86 v10.79,42.86 | R2.2 44.45,39.05 v45.4,38.1 46.35,39.05 R3.2 | RN1.8 RN1.7 RN1.6 RN1.5 44.45,33.92 v44.45,34.61 | RN4.4 44.29,21.32 v44.29,20.48 | R4.2 27.62,13.02 28.57,13.02 28.89,12.7 v28.89,11.75 | R10.2 v1.91,21.91 R9.2 | v1.59,14.92 2.44,14.92 C18.1 3.97,15.03 RN6.8 RN6.7 RN6.6 RN6.5 | v5.4,10.16 4.66,10.16 C19.1 | R6.2 C19.1 | C19.1 R5.2 | R7.2 2.65,8.15 C19.1 | v53.02,35.88
  Top 0.406: v28.89,11.75 C13.1 27.62,11.33 27.62,9.84 28.57,8.89 L1.P$1 28.26,8.26 28.26,6.67 26.67,5.08 IC2.4 | JTAG.1 v53.02,35.88 JTAG.2
  pour Supply: -1.27,81.28 81.28,81.28 81.28,-1.27 -1.27,-1.27 -1.27,20.95
+5V  (via drill 0.3)
  Top 0.203: v37.78,10.16 38.44,10.14
  Top 0.305: 38.44,10.14 IC3.20
  Top 0.406: USB1.1 34.9,5.43 34.61,5.71 | 34.61,5.71 33.02,5.71 32.38,5.08 | 32.38,5.08 30.58,3.28 C12.1 30.48,3.17 IC2.1 27.94,3.17 27.3,3.81 27.3,4.45 27.94,5.08 IC2.3 | 34.61,5.71 v34.61,6.99 | C14.1 31.11,6.35 32.38,5.08
  Bottom 0.305: v34.61,6.99 v37.78,10.16
DAC1  (via drill 0.3)
  Top 0.203: IC1.29 26.3,19.74 v25.72,20.32
  Bottom 0.203: v25.72,20.32 25.72,2.22 A4.1
GND  (via drill 0.3)
  Top 0.203: IC3.7 31.12,11.44 C15.2 v31.11,10.48 | IC3.25 38.68,13.39 v38.42,13.65 38.8,14.04 IC3.26 | IC3.18 41.22,8.84 41.59,9.21 v41.59,9.84 41.59,10.48 41.28,10.79 IC3.21 | PWR.C v28.89,14.61 | v3.17,31.43 4.03,31.43 C20.2 4.66,30.8 5.71,30.8 6,30.51 IC4.47 | IC4.15 6.5,19.68 6.19,19.37 6.13,19.37 C24.2 6.03,18.84 v6.03,18.1 | IC4.19 8.51,19.54 C22.2 9.21,18.84 v9.21,18.1 | IC1.20 21.37,22.54 C1.2 20.74,21.91 20.22,21.91 C3.2 19.37,21.06 v19.37,20.32 19.37,18.95 C2.2 | IC1.27 25.3,17.26 C9.2 | v16.83,19.05 C26.- 15.77,19.2 R11.1 | C25.2 v12.38,17.78 | Q1.2 18.96,28.42 v20,28.42 20.69,28.42 C7.2 21.89,27.54 IC1.10 | C9.2 | C9.2 v23.65,16.67 | IC4.35 IC4.36 14.6,28.15 C21.2 14.61,28.47 14.61,29.84 | 14.61,29.84 C23.2 | 14.61,29.84 v15.24,29.84 | C10.2 21.17,31.65 19.37,29.84 v19.37,29.69 | IC1.94 27.8,32.56 27.62,32.38 25.4,32.38 25.3,32.49 IC1.99 25.3,34.92 C11.2 26.04,35.66 v26.04,36.51 | IC1.74 39.69,31.54 C8.2 40.42,32.07 v41.27,32.07 | C5.2 40.42,28.89 v41.27,28.89 | 41.65,17.94 C6.2 | 41.65,17.94 v42.23,17.94 | C4.2 41.65,17.94 | 41.65,17.94 | RESET.1 51.91,1.59 v50.48,1.59 | RESET.2 42.92,1.59 v44.45,1.59 | WF1.1 33.34,39.69 32.38,40.64 31.54,40.64 C17.2 31.01,40.96 v29.84,40.96 | WF2.1 14.29,39.69 13.34,40.64 12.48,40.64 C16.2 11.96,40.96 v10.79,40.96 | RN4.2 RN4.1 44.29,23.13 v44.29,23.97 | v1.59,16.83 2.44,16.83 C18.2 | 4.76,11.43 4.55,11.64 C19.2 v4.45,12.7
  Top 0.406: IC2.2 29.21,4.13 30.16,5.08 | 30.16,5.08 C12.2 v30.48,6.03 | C13.2 v24.45,11.75 | 30.16,5.08 | USB1.5 37.49,5.43 v37.78,5.71 | JTAG.4 JTAG.6 JTAG.8 JTAG.10 JTAG.12 JTAG.14 JTAG.16 JTAG.18 JTAG.20 56.36,12.95 v56.36,11.59 | C14.2 v31.11,10.48
  Bottom 0.406: v37.78,5.71 37.47,6.03 v30.48,6.03
  pour GND: -0.64,80.64 80.64,80.64 80.64,-0.64 -0.64,-0.64
JTAG-SRST1
  Top 0.203: RN3.7 49.37,18.35 JTAG.15
JTAG-TCK1
  Top 0.203: 45.22,25.72 JTAG.9 | 45.22,25.72 RN2.5 | RN4.8 45.22,25.72
JTAG-TDI1  (via drill 0.3)
  Top 0.203: RN2.7 45.97,29.78 v46.35,30.16 46.99,30.8 JTAG.5 | v46.35,32.7 46.29,32.77 RN1.2
  Bottom 0.203: v46.35,30.16 v46.35,32.7
JTAG-TDO1
  Top 0.203: JTAG.13 47.62,20.64 46.91,21.35 RN4.5 RN3.8
JTAG-TMS1  (via drill 0.3)
  Top 0.203: RN2.6 46.29,29.28 v46.35,29.21 47.31,28.26 JTAG.7 | v46.35,33.66 46.12,33.9 RN1.4
  Bottom 0.203: v46.35,29.21 45.72,29.84 45.72,33.02 v46.35,33.66
JTAG-TRST1
  Top 0.203: JTAG.3 47.94,33.34 46.67,32.07 45.3,32.07 RN1.1 RN2.8
LED0  (via drill 0.3)
  Top 0.203: IC1.65 39.96,27.04 v40.01,26.99 | v47.31,45.09 LED2.C
  Bottom 0.203: v40.01,26.99 41.59,26.99 45.09,30.48 45.09,36.2 46.35,37.47 46.35,44.13 v47.31,45.09
LED1  (via drill 0.3)
  Top 0.203: IC1.66 39.6,27.54 v40.01,27.94 | v44.77,45.09 LED1.C
  Bottom 0.203: v40.01,27.94 41.91,27.94 43.81,29.84 43.81,44.13 v44.77,45.09
MII_COL  (via drill 0.3)
  Top 0.203: IC1.26 24.8,20.35 27.3,22.86 v27.3,28.57 | RN9.2 9.46,33.75 9.68,33.97 11.11,33.97 v11.43,33.66
  Bottom 0.203: v27.3,28.57 26.35,28.57 22.7,32.23 16.99,32.23 15.56,33.66 v11.43,33.66
MII_CRS  (via drill 0.3)
  Top 0.203: IC1.23 24.21,21.04 26.04,22.86 26.04,26.67 v26.67,27.3 | RN10.4 14.84,32.78 v15.56,32.07
  Bottom 0.203: v26.67,27.3 26.35,27.3 22.38,31.27 16.35,31.27 v15.56,32.07
MII_INT  (via drill 0.3)
  Top 0.203: IC4.7 5.46,25.15 v6.99,26.67 | IC1.81 34.3,26.04 v33.66,25.4
  Bottom 0.203: v6.99,26.67 10.16,26.67 10.79,27.3 18.1,27.3 19.84,25.56 23.34,25.56 24.77,24.13 33.34,24.13 33.66,24.45 v33.66,25.4
MII_MDC  (via drill 0.3)
  Top 0.203: IC4.31 11.5,25.65 v11.11,26.04 | IC1.16 22,24.54 v21.59,24.13
  Bottom 0.203: v21.59,24.13 21.11,24.61 19.53,24.61 18.26,25.88 11.27,25.88 v11.11,26.04
MII_MDIO  (via drill 0.3)
  Top 0.203: IC4.30 14.22,25.15 v14.29,25.08 | R8.1 23.18,18.52 v23.18,19.37 23.18,20.02 IC1.25
  Bottom 0.203: v23.18,19.37 21.27,21.27 17.14,21.27 14.29,24.13 v14.29,25.08
MII_RX_CLK  (via drill 0.3)
  Top 0.203: IC1.24 24.34,20.54 26.67,22.86 v26.67,26.04 | RN10.2 13.43,31.66 v13.97,31.11
  Bottom 0.203: v26.67,26.04 26.35,26.04 22.07,30.32 15.72,30.32 15.24,30.8 14.29,30.8 v13.97,31.11
MII_RX_DV  (via drill 0.3)
  Top 0.203: IC1.32 27.8,21.45 27.94,21.59 v27.94,26.04 | RN10.3 14.2,32.16 v14.92,31.43
  Bottom 0.203: v27.94,26.04 27.3,26.67 26.35,26.67 22.23,30.8 16.19,30.8 15.56,31.43 v14.92,31.43
MII_RX_ER  (via drill 0.3)
  Top 0.203: IC1.47 35.3,19.31 31.11,23.5 v31.11,26.67 | RN9.1 10.5,33.31 v10.79,33.02
  Bottom 0.203: v31.11,26.67 28.26,26.67 26.99,27.94 26.35,27.94 22.54,31.75 16.83,31.75 15.56,33.02 v10.79,33.02
MII_RXD0  (via drill 0.3)
  Top 0.203: IC1.33 28.3,21.31 28.57,21.59 v28.57,27.3 | RN9.3 8.96,33.88 9.53,34.45 13.81,34.45 15.56,32.7 19.37,32.7 v19.68,33.02
  Bottom 0.203: v28.57,27.3 27.94,27.94 27.94,28.89 27.62,29.21 26.35,29.21 22.54,33.02 v19.68,33.02
MII_RXD1  (via drill 0.3)
  Top 0.203: IC1.34 28.8,21.18 29.21,21.59 v29.21,27.94 | RN9.4 8.33,33.89 9.37,34.92 13.97,34.92 15.56,33.34 v18.1,33.34
  Bottom 0.203: v29.21,27.94 29.21,28.26 27.62,29.84 26.35,29.84 22.54,33.66 19.37,33.66 19.05,33.34 v18.1,33.34
MII_RXD2  (via drill 0.3)
  Top 0.203: IC1.35 29.3,21.04 29.84,21.59 v29.84,27.3 | RN7.1 9.16,35.4 14.13,35.4 15.56,33.97 v18.73,33.97
  Bottom 0.203: v29.84,27.3 29.84,28.26 27.62,30.48 26.67,30.48 23.02,34.13 18.89,34.13 v18.73,33.97
MII_RXD3  (via drill 0.3)
  Top 0.203: IC1.36 29.8,20.91 30.48,21.59 v30.48,27.94 | RN7.2 6.92,34.22 8.57,35.88 14.29,35.88 15.56,34.61 v18.1,34.61
  Bottom 0.203: v30.48,27.94 30.48,28.26 27.62,31.11 26.67,31.11 23.18,34.61 v18.1,34.61
MII_TX_CLK  (via drill 0.3)
  Top 0.203: IC1.18 24.49,23.54 25.4,24.45 25.4,27.62 v28.89,31.11 | RN7.3 6.42,34.36 8.41,36.35 14.45,36.35 15.56,35.24 v17.46,35.24
  Bottom 0.203: v28.89,31.11 28.26,31.75 26.67,31.75 23.18,35.24 v17.46,35.24
MII_TX_EN  (via drill 0.3)
  Top 0.203: IC1.48 35.8,19.45 31.75,23.5 v31.75,27.62 | RN7.4 5.79,34.37 8.26,36.83 14.61,36.83 15.56,35.88 v16.83,35.88
  Bottom 0.203: v31.75,27.62 31.75,29.21 28.57,32.38 26.99,32.38 23.5,35.88 v16.83,35.88
MII_TXD0  (via drill 0.3)
  Top 0.203: IC1.51 35.84,20.04 32.38,23.5 v32.38,25.4 | v3.81,35.24 3.81,34.5 RN5.1
  Bottom 0.203: v32.38,25.4 26.35,25.4 22.7,29.05 18.89,29.05 18.73,29.21 11.43,29.21 6.99,33.66 4.76,33.66 3.81,34.61 v3.81,35.24
MII_TXD1  (via drill 0.3)
  Top 0.203: IC1.52 35.98,20.54 33.02,23.5 v33.02,24.77 | v3.17,35.88 3.11,35.81 RN5.2
  Bottom 0.203: v33.02,24.77 26.35,24.77 23.5,27.62 19.68,27.62 18.73,28.57 11.27,28.57 6.68,33.17 4.62,33.17 3.17,34.61 v3.17,35.88
MII_TXD2  (via drill 0.3)
  Top 0.203: IC1.17 24.35,24.04 24.77,24.45 v24.77,25.08 | v2.54,35.24 2.61,35.17 RN5.3
  Bottom 0.203: v24.77,25.08 24.77,25.72 23.34,27.15 19.53,27.15 18.73,27.94 11.11,27.94 6.35,32.7 4.45,32.7 2.54,34.61 v2.54,35.24
MII_TXD3  (via drill 0.3)
  Top 0.203: IC1.95 v27.3,35.23 v27.3,35.24 | RN5.4 1.91,34.5 1.91,35.56 2.86,36.51 v4.13,36.51
  Bottom 0.203: v27.3,35.24 24.77,35.24 23.5,36.51 v4.13,36.51
N$1
  Top 0.203: IC4.3 3.01,27.15 2.54,27.62 2.54,31.75 3.73,32.94 RN5.8
N$2
  Top 0.203: IC4.4 2.88,26.65 2.06,27.46 2.06,31.91 3.11,32.95 RN5.7
N$3
  Top 0.203: IC4.5 2.74,26.15 1.59,27.3 1.59,32.07 2.61,33.09 RN5.6
N$4
  Top 0.203: IC4.6 2.61,25.65 1.11,27.15 1.11,32.23 1.98,33.1 RN5.5
N$5  (via drill 0.3)
  Top 0.203: IC4.1 6.14,28.15 v6.35,27.94 | RN7.6 6.42,32.45 v6.03,32.07
  Bottom 0.203: v6.35,27.94 6.03,28.26 v6.03,32.07
N$6  (via drill 0.3)
  Top 0.203: v5.71,27.3 5.37,27.65 IC4.2 | RN7.5 5.79,32.78 5.4,32.38 v5.4,31.43
  Bottom 0.203: v5.4,31.43 5.4,27.62 v5.71,27.3
N$7
  Top 0.203: RN7.8 7.54,31.99 7,31.45 IC4.45
N$8
  Top 0.203: RN7.7 6.92,32 6.5,31.59 IC4.46
N$9
  Top 0.203: IC4.43 8.01,31.18 8.96,32.13 RN9.6
N$10
  Top 0.203: IC4.44 7.5,31.32 8.33,32.15 RN9.5
N$11
  Top 0.203: IC4.42 8.51,31.05 9.46,32 RN9.7
N$12
  Top 0.203: IC4.41 9.01,30.91 10.08,31.99 RN9.8
N$13
  Top 0.203: IC4.39 10.01,30.64 11.52,32.16 RN10.6
N$14
  Top 0.203: IC4.38 10.51,30.51 11.66,31.66 RN10.7
N$15
  Top 0.203: IC4.40 9.51,30.78 11.51,32.78 RN10.5
N$16  (via drill 0.3)
  Top 0.203: IC4.20 9.01,22.43 v8.57,22.86 | v0.95,19.05 1.8,19.05 R9.1
  Bottom 0.203: v8.57,22.86 8.57,23.81 7.62,24.77 6.35,24.77 0.95,19.37 v0.95,19.05
N$17
  Top 0.203: R6.1 7.41,3.49 17.17,3.49 ETH.13
N$18
  Top 0.203: IC4.34 13.81,27.15 13.97,27.3 16.15,27.3 Q1.3
N$19
  Top 0.203: R7.1 2.54,6.35 6.92,1.97 ETH.11
N$20
  Top 0.203: IC4.24 11.01,21.91 12.8,21.91 R11.2
N$21
  Top 0.203: C24.1 8.01,19.54 IC4.18 8.01,23.56 8.89,24.45 9.53,24.45 | 9.53,24.45 9.53,23.97 10,23.5 10,22.54 10.51,22.04 IC4.23 10.51,20.29 10.79,20 11.85,20 C25.1 12.44,20.54 C26.+ | 9.53,24.45 9.53,26.67 11.01,28.15 IC4.37 12.24,29.6 C23.1
N$22  (via drill 0.3)
  Top 0.203: IC4.21 9.51,23.2 v9.21,23.5 | v0.95,24.77 1.8,24.77 R10.1
  Bottom 0.203: v9.21,23.5 9.21,23.81 7.62,25.4 1.59,25.4 v0.95,24.77
N$23  (via drill 0.3)
  Top 0.203: v10.79,22.54 11.4,23.15 IC4.26 12.48,23.18 13.49,23.18 13.59,23.09 RN8.3
  Bottom 0.203: v10.79,22.54 17.78,15.56 17.78,14.61 16.51,13.34 16.51,7.96 ETH.12
N$24  (via drill 0.3)
  Top 0.203: v10.79,23.5 10.95,23.65 IC4.27 13.49,23.65 13.56,23.59 RN8.2 | 100MBIT.C v0.95,5.71
  Bottom 0.203: v10.79,23.5 9.53,22.23 8.26,22.23 7.94,22.54 7.94,23.81 7.62,24.13 6.35,24.13 2.54,20.32 2.54,7.3 v0.95,5.71
N$25  (via drill 0.3)
  Top 0.203: v10.16,24.13 10.18,24.15 IC4.28 14.09,24.15 RN8.1
  Bottom 0.203: v10.16,24.13 11.11,24.13 11.75,23.5 13.65,23.5 20.32,16.83 20.32,11.11 17.78,8.57 17.78,5.08 20.89,1.97 ETH.14
N$26  (via drill 0.3)
  Top 0.203: RN6.4 4.89,17.33 v4.45,17.78 4.13,18.1 4.13,19.68 5.5,21.06 IC4.13
  Bottom 0.203: ETH.6 14.29,17.14 5.08,17.14 v4.45,17.78
N$27  (via drill 0.3)
  Top 0.203: RN6.3 5.33,16.12 v5.71,16.51 5.71,17.46 4.76,18.41 4.76,19.68 5.08,20 5.71,20 6,20.29 IC4.14
  Bottom 0.203: v5.71,16.51 12.38,16.51 ETH.4
N$28  (via drill 0.3)
  Top 0.203: IC4.16 7,22.52 v6.67,22.86 | v5.71,15.56 5.65,15.62 RN6.2
  Bottom 0.203: v6.67,22.86 3.81,20 3.81,17.46 v5.71,15.56 8.89,15.56 10.79,13.65 11.43,13.65 ETH.3
N$29  (via drill 0.3)
  Top 0.203: IC4.17 7.5,23.29 v7.3,23.5 | v5.71,14.61 5.32,15 RN6.1
  Bottom 0.203: v7.3,23.5 6.35,23.5 3.17,20.32 3.17,17.14 v5.71,14.61 7.94,14.61 ETH.1
N$30
  Top 0.203: RN4.7 46.92,22.48 47.62,23.18 JTAG.11
N$31  (via drill 0.3)
  Top 0.203: IC1.40 31.8,17.51 v31.43,17.14
  Bottom 0.203: v31.43,17.14 31.43,15.56 27.3,11.43 E9.1
N$32  (via drill 0.3)
  Top 0.203: IC1.42 32.8,17.56 v32.38,17.14
  Bottom 0.203: v32.38,17.14 32.38,15.56 29.84,13.02 E11.1
N$33
  Top 0.203: 2.44,11.54 R5.1 0.95,10.06 100MBIT.A
N$41
  Top 0.406: IC3.16 36.43,7.54 35.55,6.65 USB1.2
N$42
  Top 0.406: IC3.15 37.05,6.89 36.2,6.03 USB1.3
N$45
  Top 0.406: IC2.5 25.4,3.17 24.77,3.81 L1.P$2
N$48
  Top 0.203: R4.1 25.72,13.34 25.72,14.29 25.62,14.51 PWR.A
N$62
  Top 0.203: IC1.73 39.98,31.04 C5.1
N$63
  Top 0.203: IC1.49 36.3,17.36 36.51,17.14 C4.1
N$67
  Top 0.203: LED2.A 47.19,42.75 46.67,42.23 46.67,41.17 R3.1
N$68
  Top 0.203: LED1.A 44.77,41.17 R2.1
PHY_RESET  (via drill 0.3)
  Top 0.203: IC4.29 11.23,24.65 v10.48,25.4 | IC1.82 33.8,27.13 v33.34,26.67
  Bottom 0.203: v10.48,25.4 10.48,26.35 10.79,26.67 18.1,26.67 19.68,25.08 23.18,25.08 24.77,23.5 33.34,23.5 34.29,24.45 34.29,25.72 v33.34,26.67
RESET_CFG  (via drill 0.3)
  Top 0.203: IC1.85 32.3,32.47 32.7,32.07 v33.02,32.07
  Bottom 0.203: v33.02,32.07 40.32,32.07 43.18,34.92 43.18,45.4 45.09,47.31 CFG.1
SPI1_MISO  (via drill 0.3)
  Top 0.203: IC1.31 27.3,21.28 v26.99,21.59 | v23.81,39.05 WF2.7
  Bottom 0.203: MISO'.1 19.68,43.81 23.81,39.69 v23.81,39.05 25.08,39.05 28.57,35.56 28.57,33.66 35.56,26.67 35.56,24.45 33.34,22.23 27.62,22.23 v26.99,21.59
SPI1_MOSI
  Top 0.203: IC1.91 29.3,35.79 22.23,42.86 20.64,42.86 19.37,44.13 WF2.6 19.37,45.4 17.14,47.62 MOSI'.1
SPI1_SCK  (via drill 0.3)
  Top 0.203: IC1.30 26.8,20.51 v26.35,20.95 | v20.64,38.1 19.37,38.1 WF2.5
  Bottom 0.203: v26.35,20.95 26.35,21.91 27.3,22.86 33.34,22.86 34.92,24.45 34.92,26.67 27.94,33.66 27.94,35.56 25.4,38.1 v20.64,38.1 19.05,39.69 19.05,44.13 CK'.1
SPI3_MISO
  Top 0.203: IC1.79 35.3,34.98 37.47,37.15 37.47,40.32 37.78,40.64 39.69,40.64 | 39.69,40.64 40.01,40.64 40.96,39.69 WF1.7 | MISO.1 39.69,47.62 39.69,40.64
SPI3_MOSI
  Top 0.203: IC1.80 34.8,35.12 36.83,37.15 36.83,40.32 38.42,41.91 WF1.6 38.42,46.35 MOSI.1
SPI3_SCK  (via drill 0.3)
  Top 0.203: IC1.78 35.8,34.84 38.42,37.47 WF1.5 38.42,39.69 v39.37,39.69
  Bottom 0.203: v39.37,39.69 39.37,42.86 CK.1
SRST
  Top 0.203: IC1.14 22.04,25.54 21.59,25.08 20.32,25.08 19.21,23.97 19.05,23.97 18.73,23.65 18.73,22.33 R1.1 17.46,19.15 C2.1 | C2.1 18.2,18.31 19.37,17.14 21.91,17.14 23.5,15.56 28.89,15.56 29.53,16.19 42.23,16.19 | 42.23,16.19 43.18,17.14 43.18,17.78 43.75,18.35 RN3.2 | 42.23,16.19 42.23,6.67 RESET.4 RESET.3 | C2.1 17.78,18.84
TCK
  Top 0.203: RN2.4 43.1,28.65 41.91,29.84 41.91,33.97 40.96,34.92 37.15,34.92 36.8,34.58 IC1.76
TDI
  Top 0.203: RN2.2 43.88,29.78 42.39,31.27 42.39,34.13 41.12,35.4 36.99,35.4 36.3,34.71 IC1.77
TDO  (via drill 0.3)
  Top 0.203: v43.18,19.68 43.89,18.97 RN3.1 | v31.11,32.07 30.8,32.07 30.3,32.57 IC1.89
  Bottom 0.203: v31.11,32.07 31.11,31.75 v43.18,19.68
TMS  (via drill 0.3)
  Top 0.203: RN2.3 43.43,29.28 v42.55,30.16 | v36.83,30.48 36.88,30.54 IC1.72
  Bottom 0.203: v42.55,30.16 37.15,30.16 v36.83,30.48
TRST  (via drill 0.3)
  Top 0.203: IC1.90 29.8,32.12 30.48,31.43 v32.38,31.43 | v43.18,31.43 43.29,31.43 RN2.1
  Bottom 0.203: v32.38,31.43 32.7,31.11 42.86,31.11 v43.18,31.43
USART1_RX  (via drill 0.3)
  Top 0.203: v34.61,15.24 34.51,15.34 IC3.1 | IC1.69 37.29,29.04 35.88,27.62 v35.88,22.54
  Bottom 0.203: v34.61,15.24 35.88,16.51 v35.88,22.54
USART1_TX  (via drill 0.3)
  Top 0.203: v34.61,12.7 34.57,12.74 IC3.5 | IC1.68 37.42,28.54 36.51,27.62 v36.51,21.59
  Bottom 0.203: v34.61,12.7 34.61,13.65 36.51,15.56 v36.51,21.59
VCCIO
  Top 0.203: IC3.17 38.8,8.19 36.51,10.48 36.51,11.75 34.87,13.39 IC3.4 31.17,13.39 C15.1 31.11,13.33
WF1_CE
  Top 0.203: IC1.84 32.8,35.34 35.88,38.42 WF1.3 35.88,39.69 34.61,40.96 34.61,45.72 33.97,46.35 30.8,46.35 CE.1
WF1_CS  (via drill 0.3)
  Top 0.203: IC1.88 30.8,34.61 v30.16,35.24 | v35.88,43.18 WF1.4 35.88,45.4 34.29,46.99 32.7,46.99 CS.1
  Bottom 0.203: v30.16,35.24 35.88,40.96 v35.88,43.18
WF1_IRQ  (via drill 0.3)
  Top 0.203: IC1.83 33.3,34.57 v33.97,35.24 | v40.96,43.18 WF1.8 40.96,48.26 IRQ.1
  Bottom 0.203: v33.97,35.24 36.83,35.24 40.96,39.37 v40.96,43.18
WF2_CE
  Top 0.203: IC1.93 28.3,35.2 26.35,37.15 18.1,37.15 16.83,38.42 WF2.3 16.83,39.69 15.56,40.96 15.56,45.72 14.92,46.35 11.75,46.35 CE'.1
WF2_CS
  Top 0.203: IC1.92 28.8,35.34 21.91,42.23 18.73,42.23 16.83,44.13 WF2.4 16.83,45.4 15.24,46.99 13.65,46.99 CS'.1
WF2_IRQ
  Top 0.203: IC1.86 31.8,34.56 21.91,44.45 WF2.8 21.91,48.26 IRQ'.1

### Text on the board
tPlace: BS v2 | A. Ryll | Tigers Mannheim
